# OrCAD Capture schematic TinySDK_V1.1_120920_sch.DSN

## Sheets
1 CORE-PWR: size A3; title: TinySDK V1.1; company: FriendlyARM; note: CORE-PWR
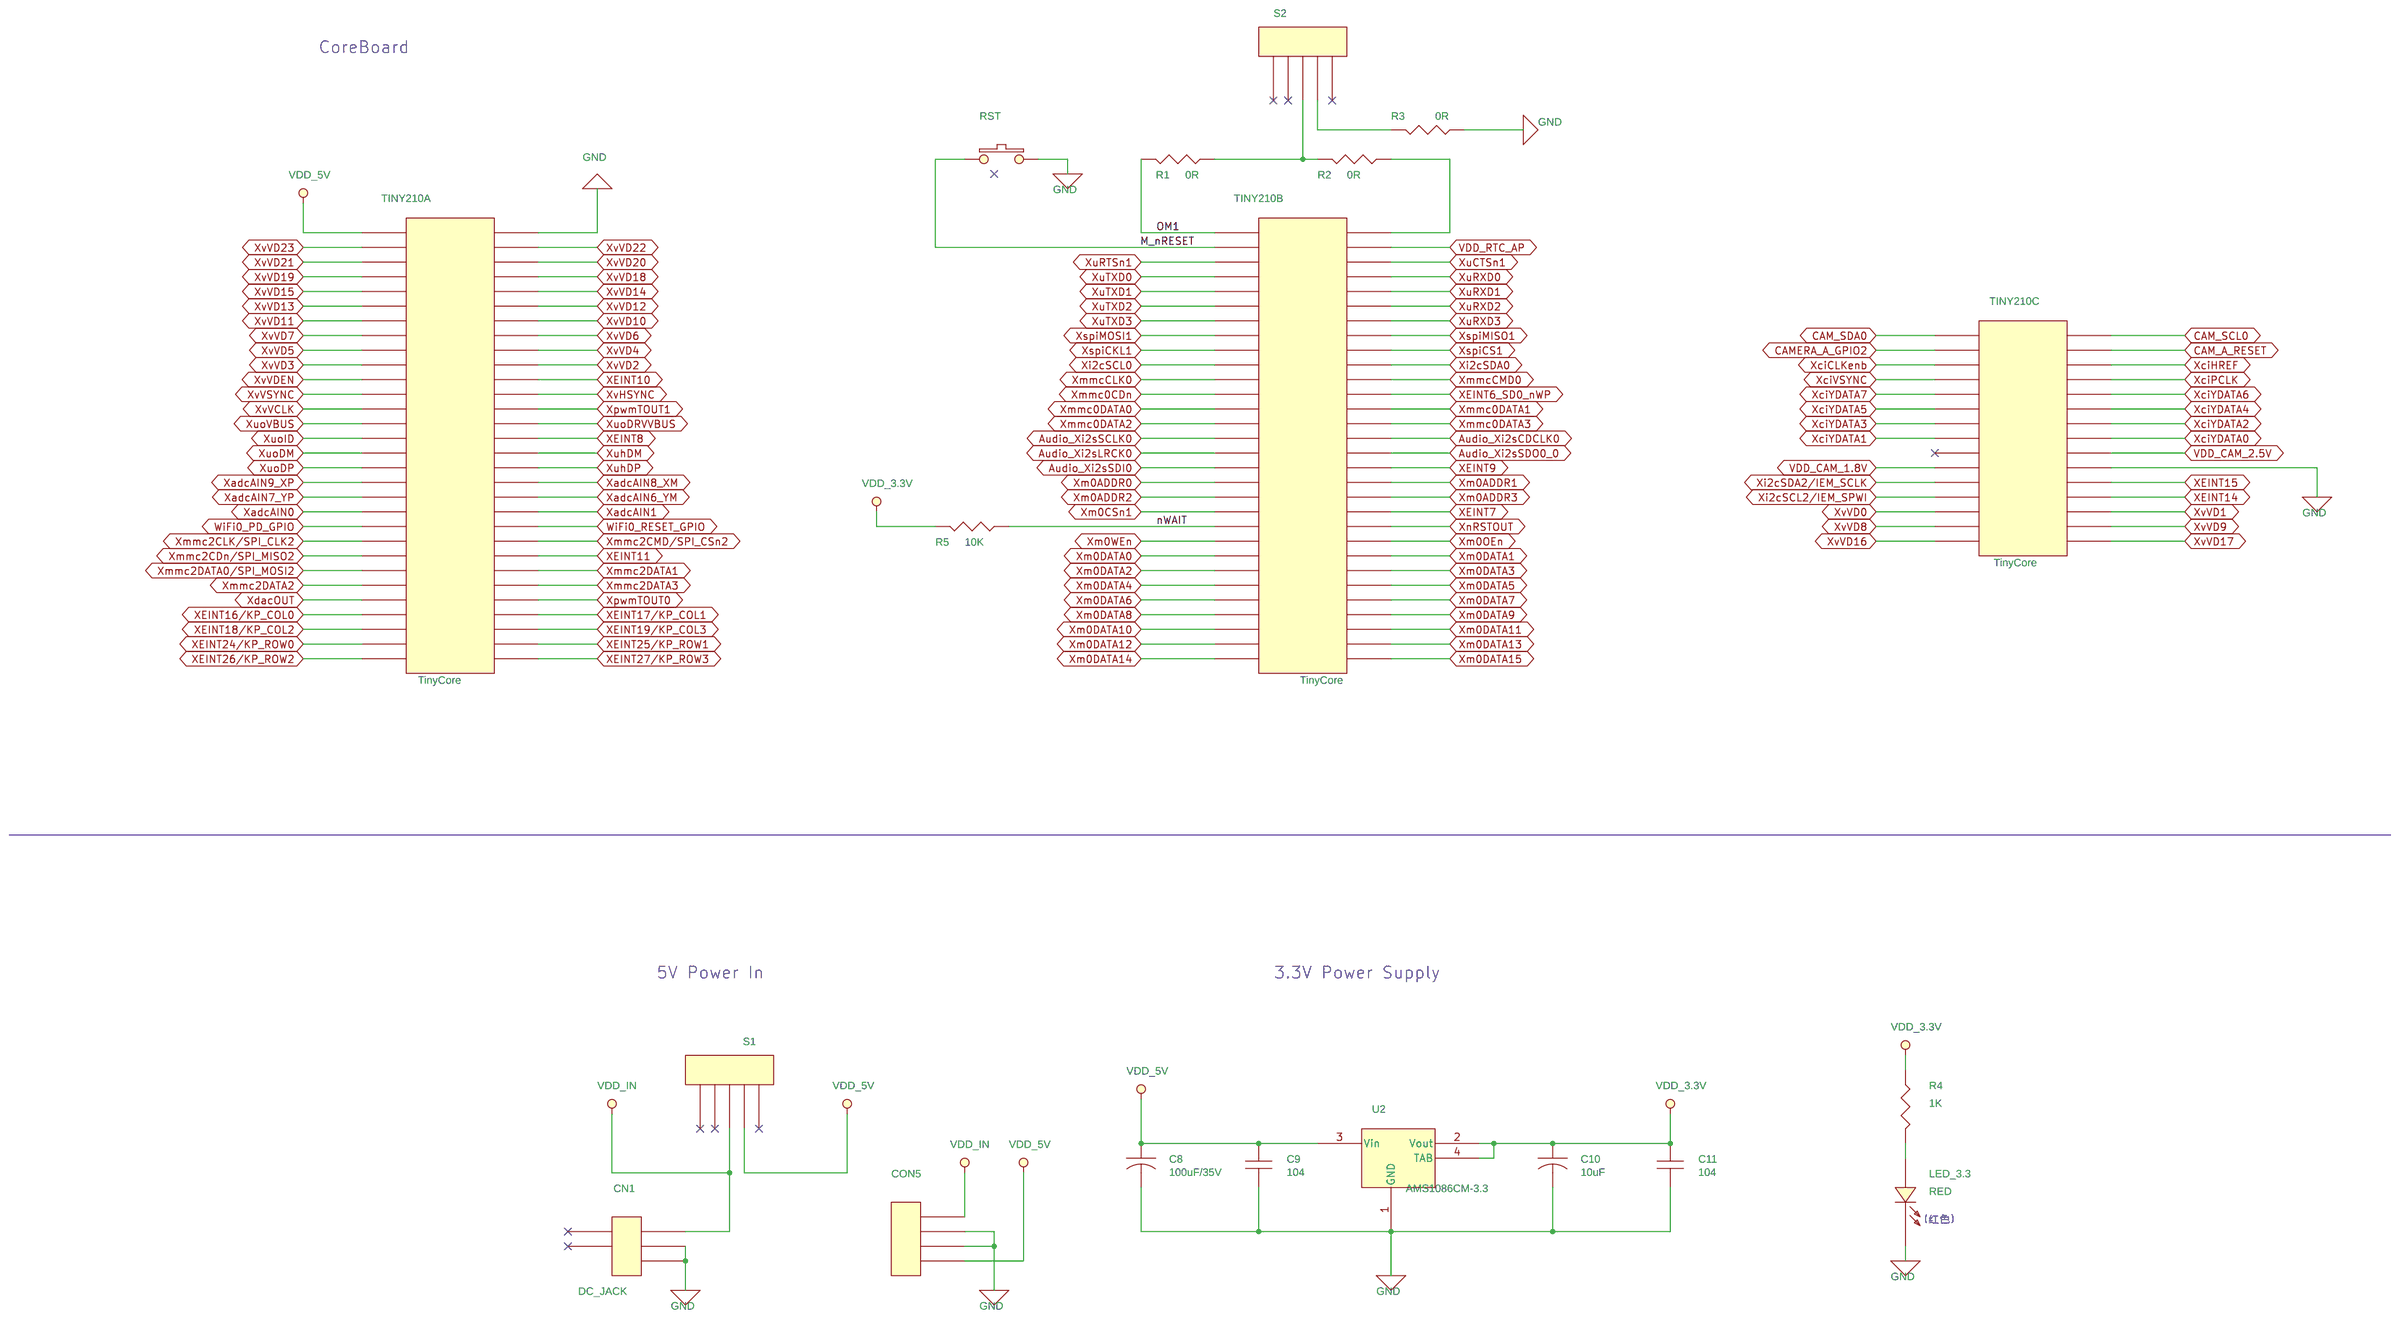
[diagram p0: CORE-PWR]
2 DM9000: size A3; note: DM9000
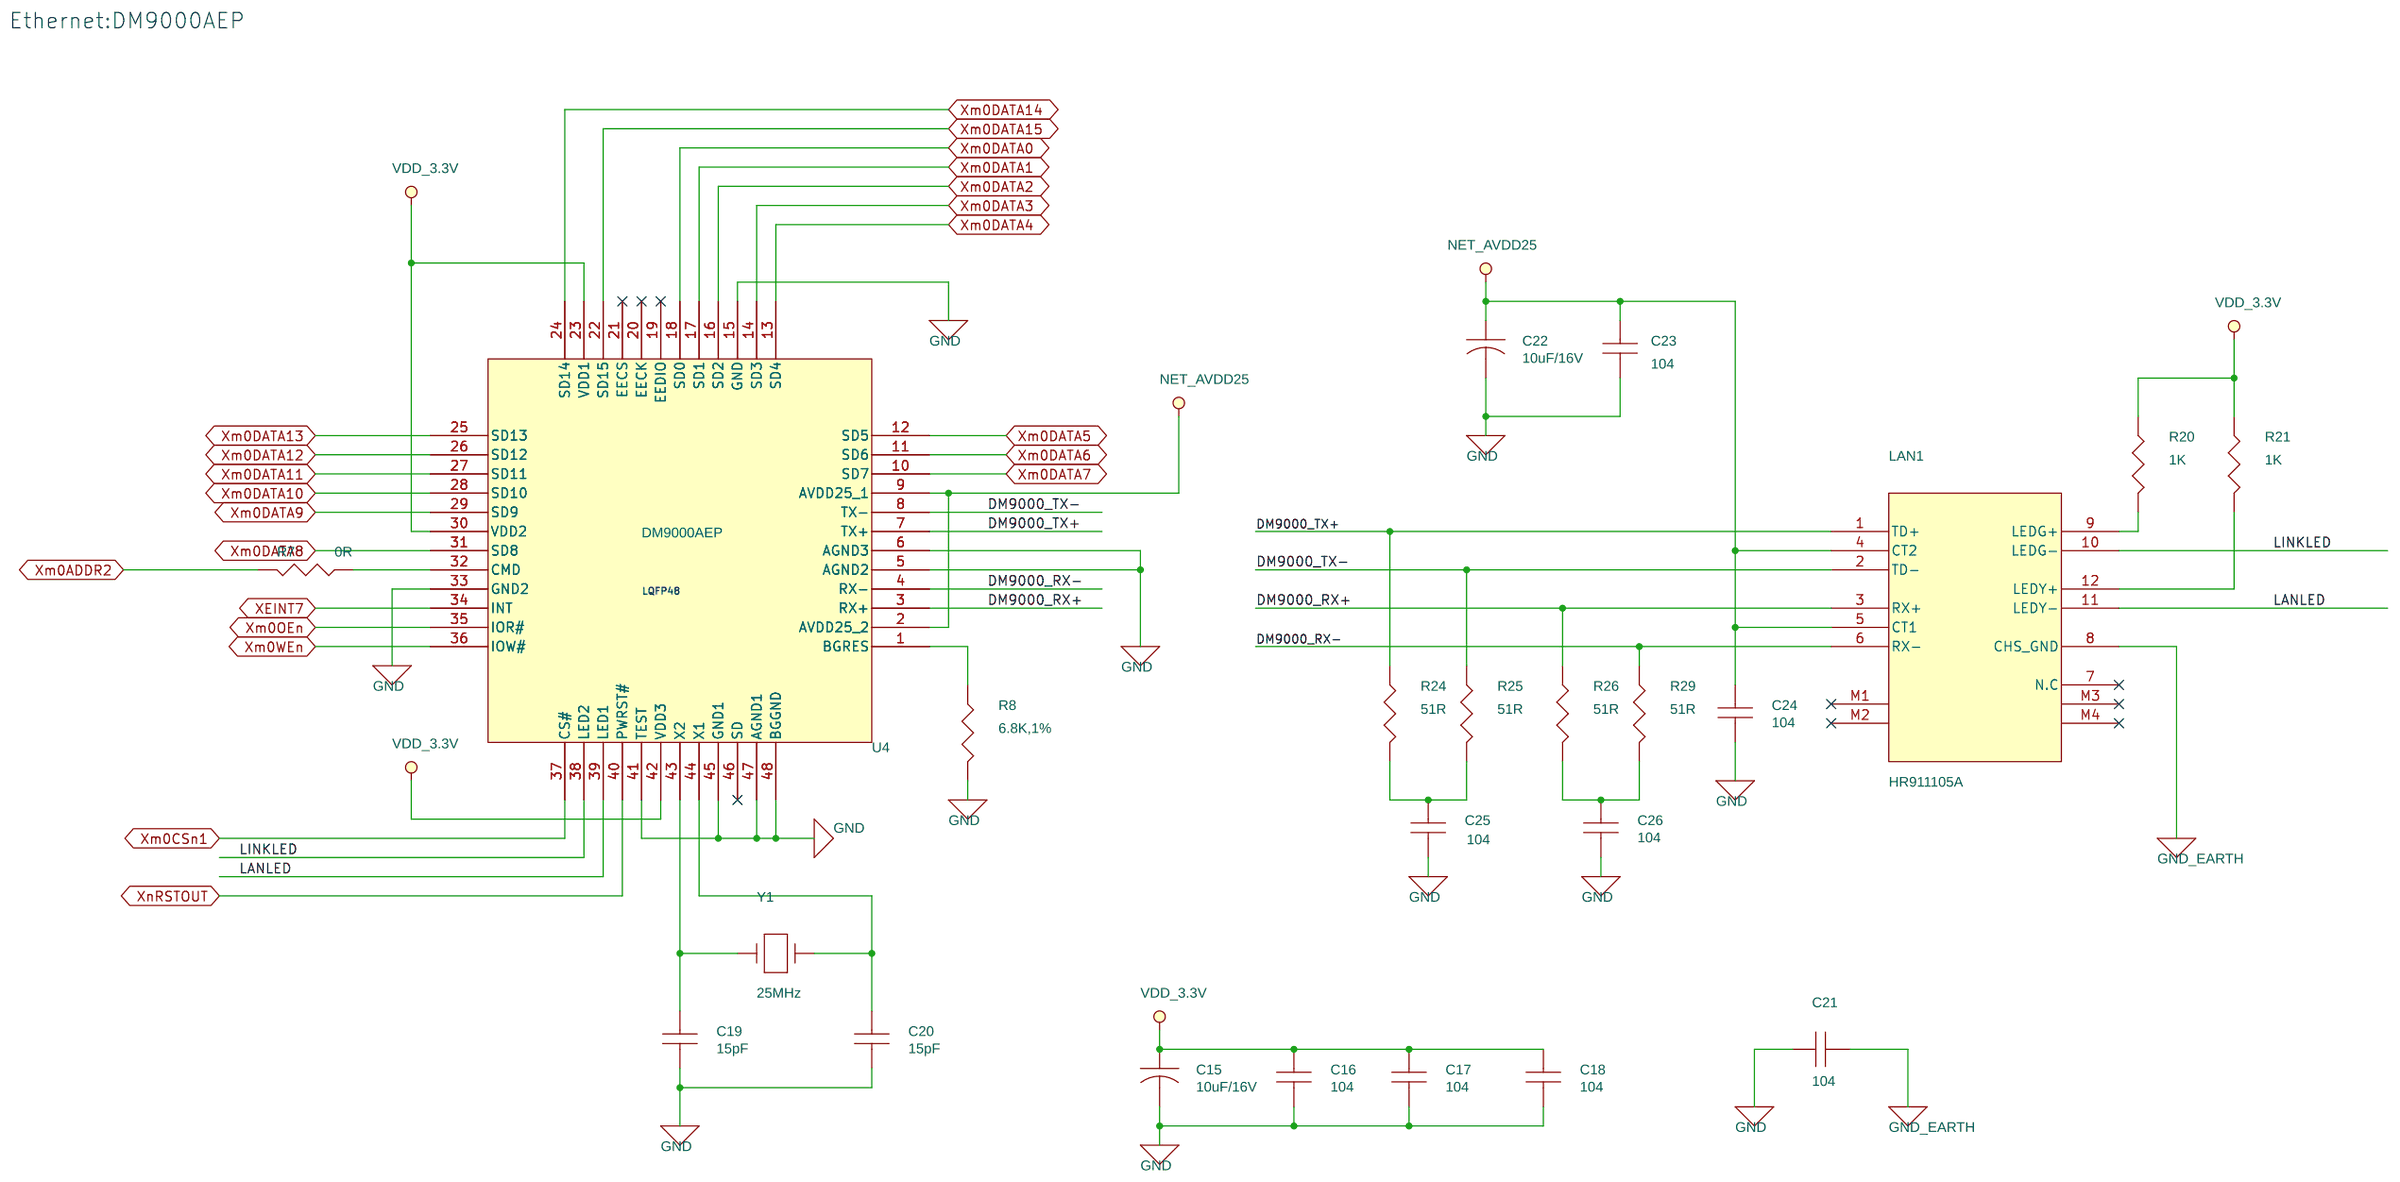
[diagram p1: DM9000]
3 Audio Codec: size A3; note: AUDIO CODEC
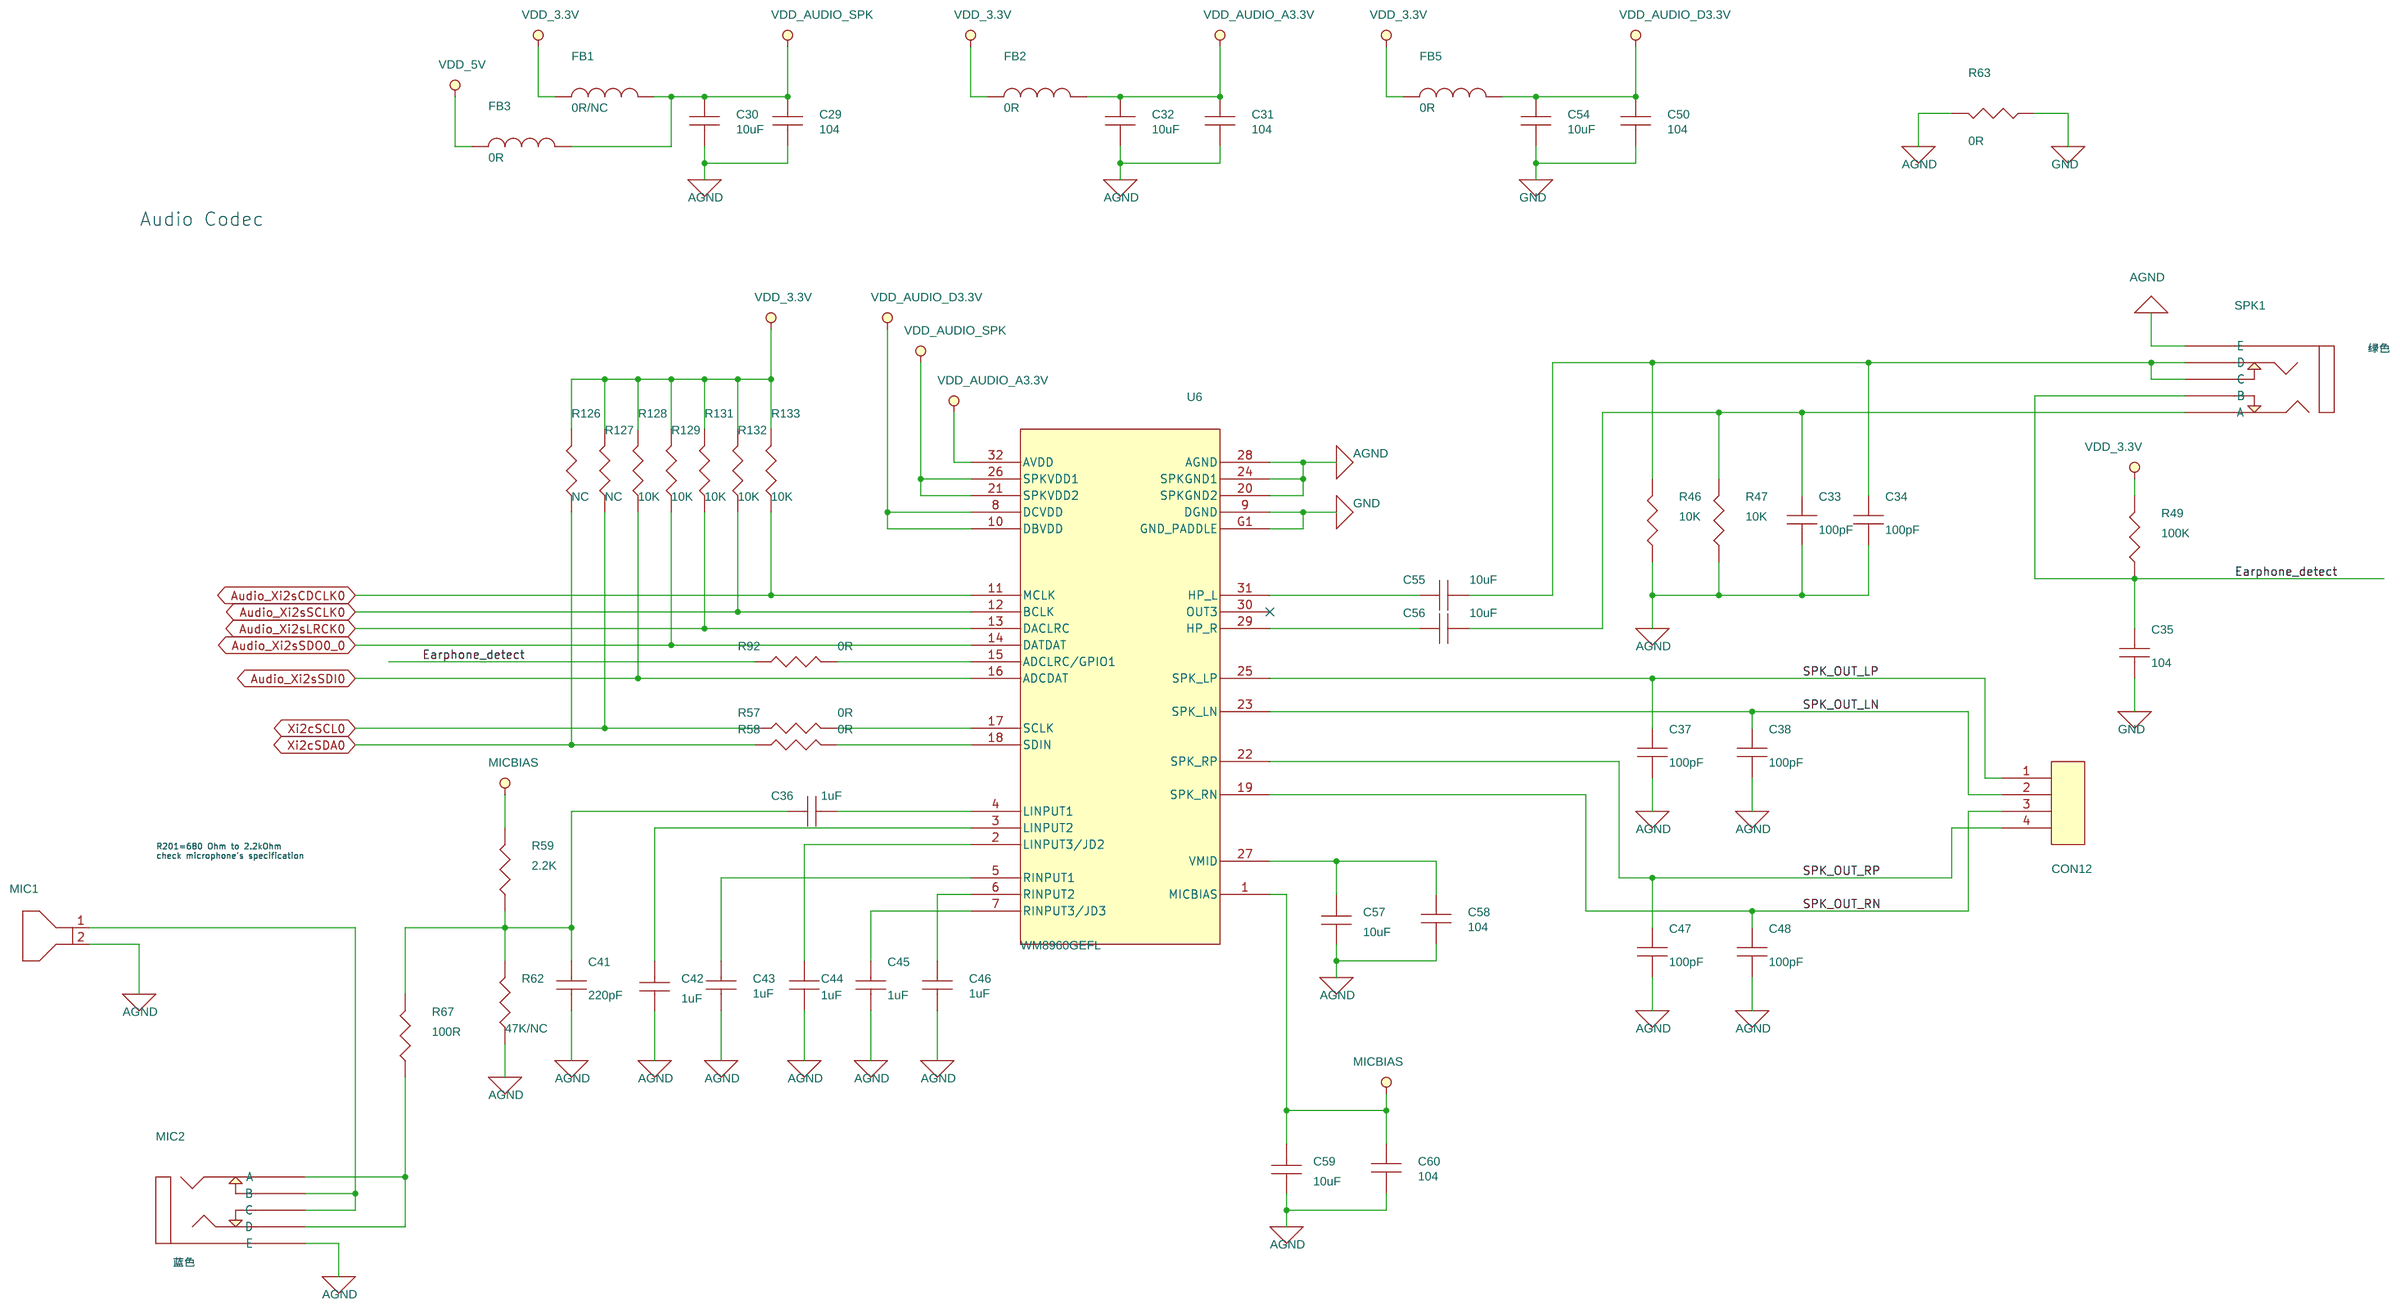
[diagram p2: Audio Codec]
4 SDIO-KEY-ETC: size A3; rev: 1.0; note: SCON-USB-ETC
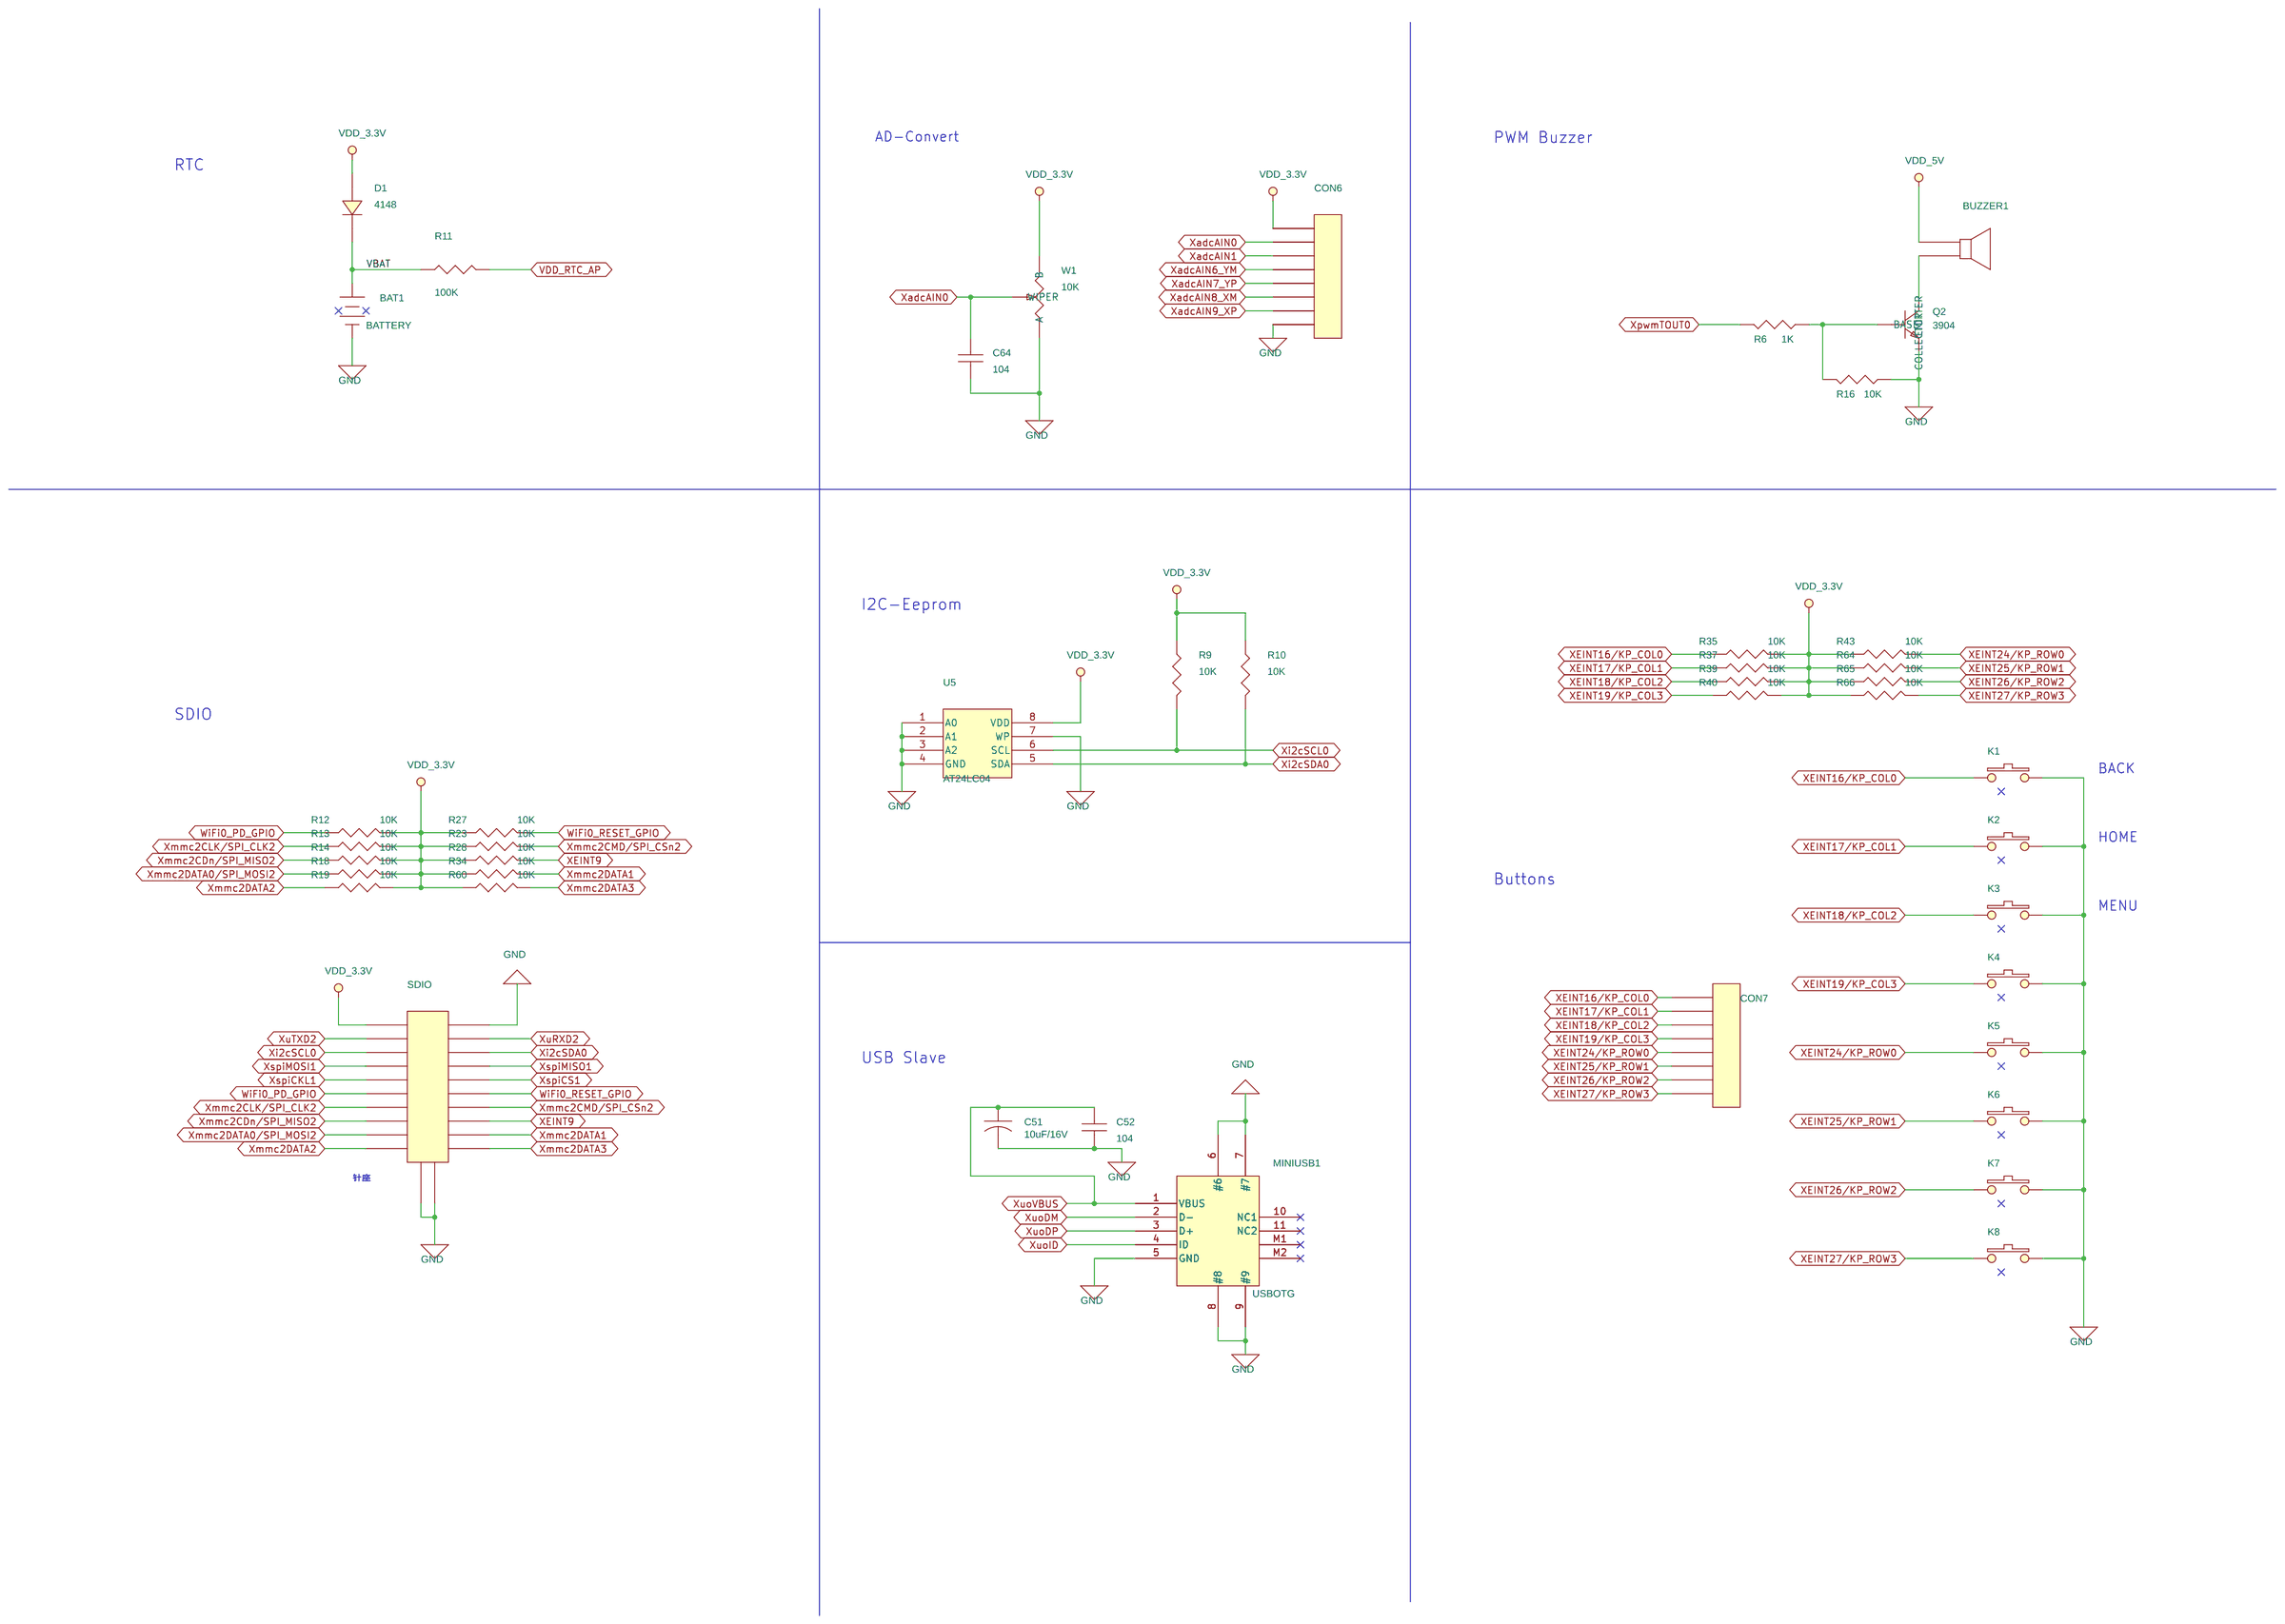
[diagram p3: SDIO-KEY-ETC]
5 LCD-UART-SDCARD-GSensor: size A3; rev: 1.0; note: LCD-UART-SDCARD-GSensor
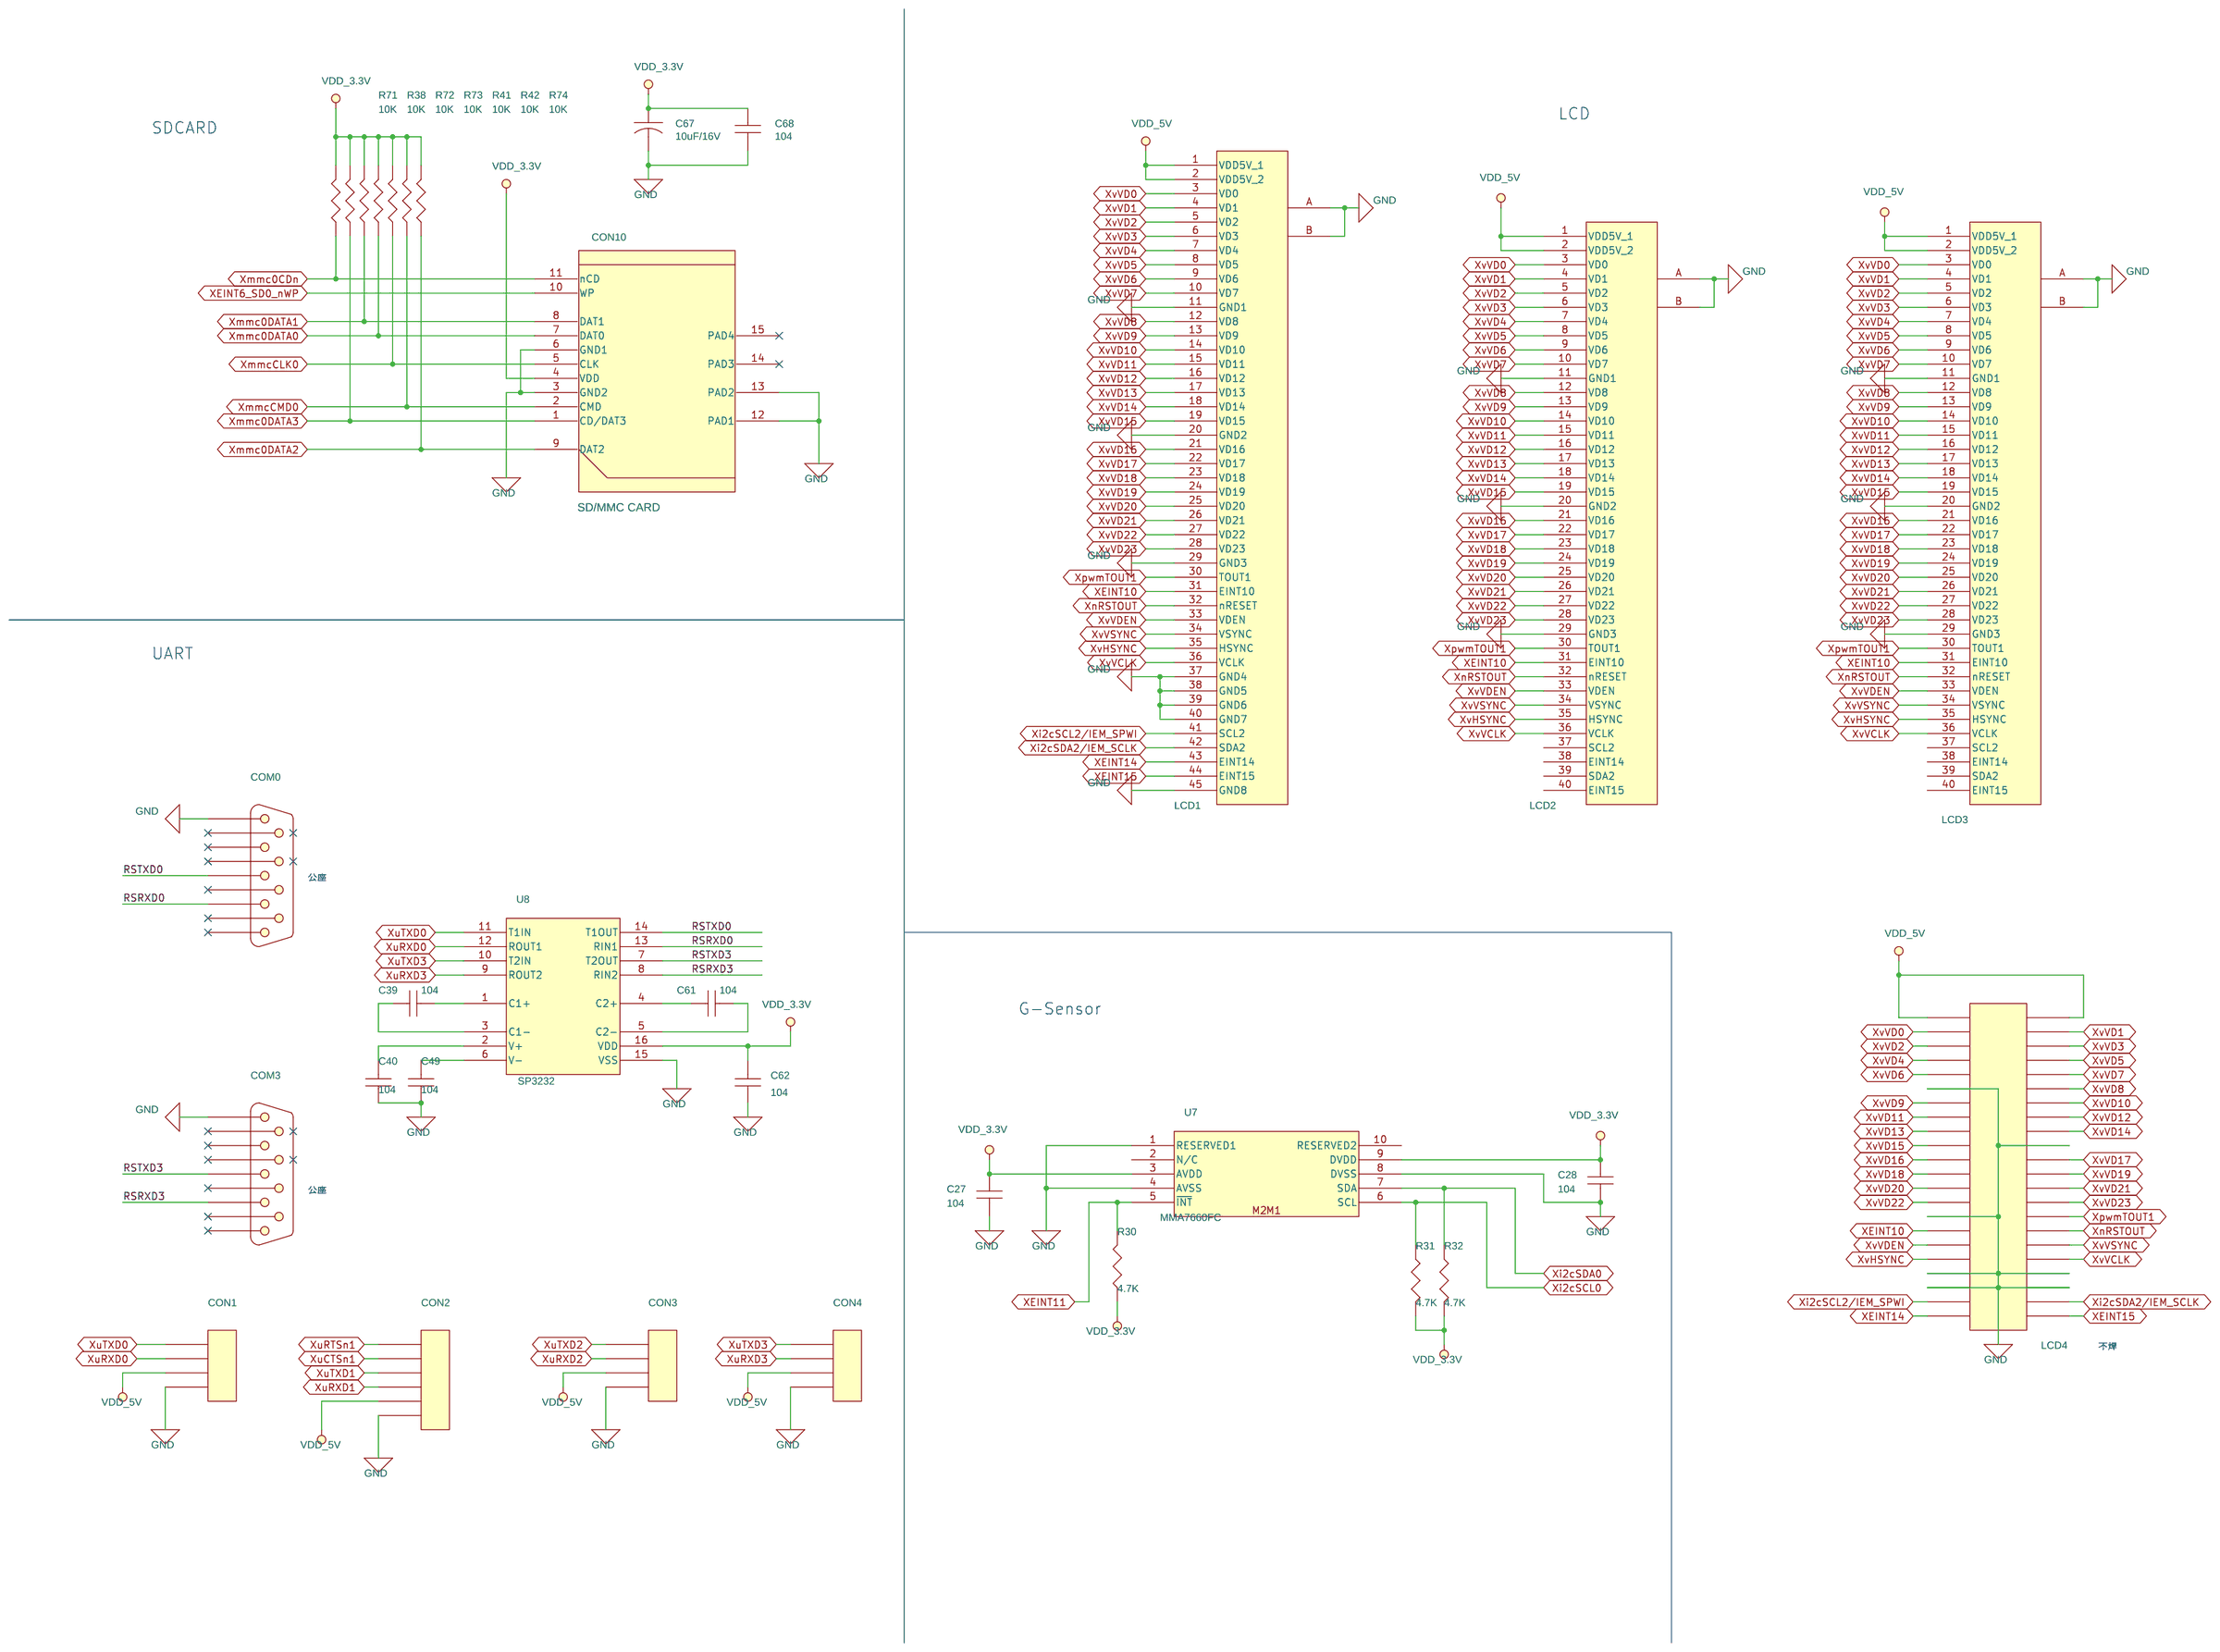
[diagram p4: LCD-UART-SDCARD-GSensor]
6 TVP5150: size A3
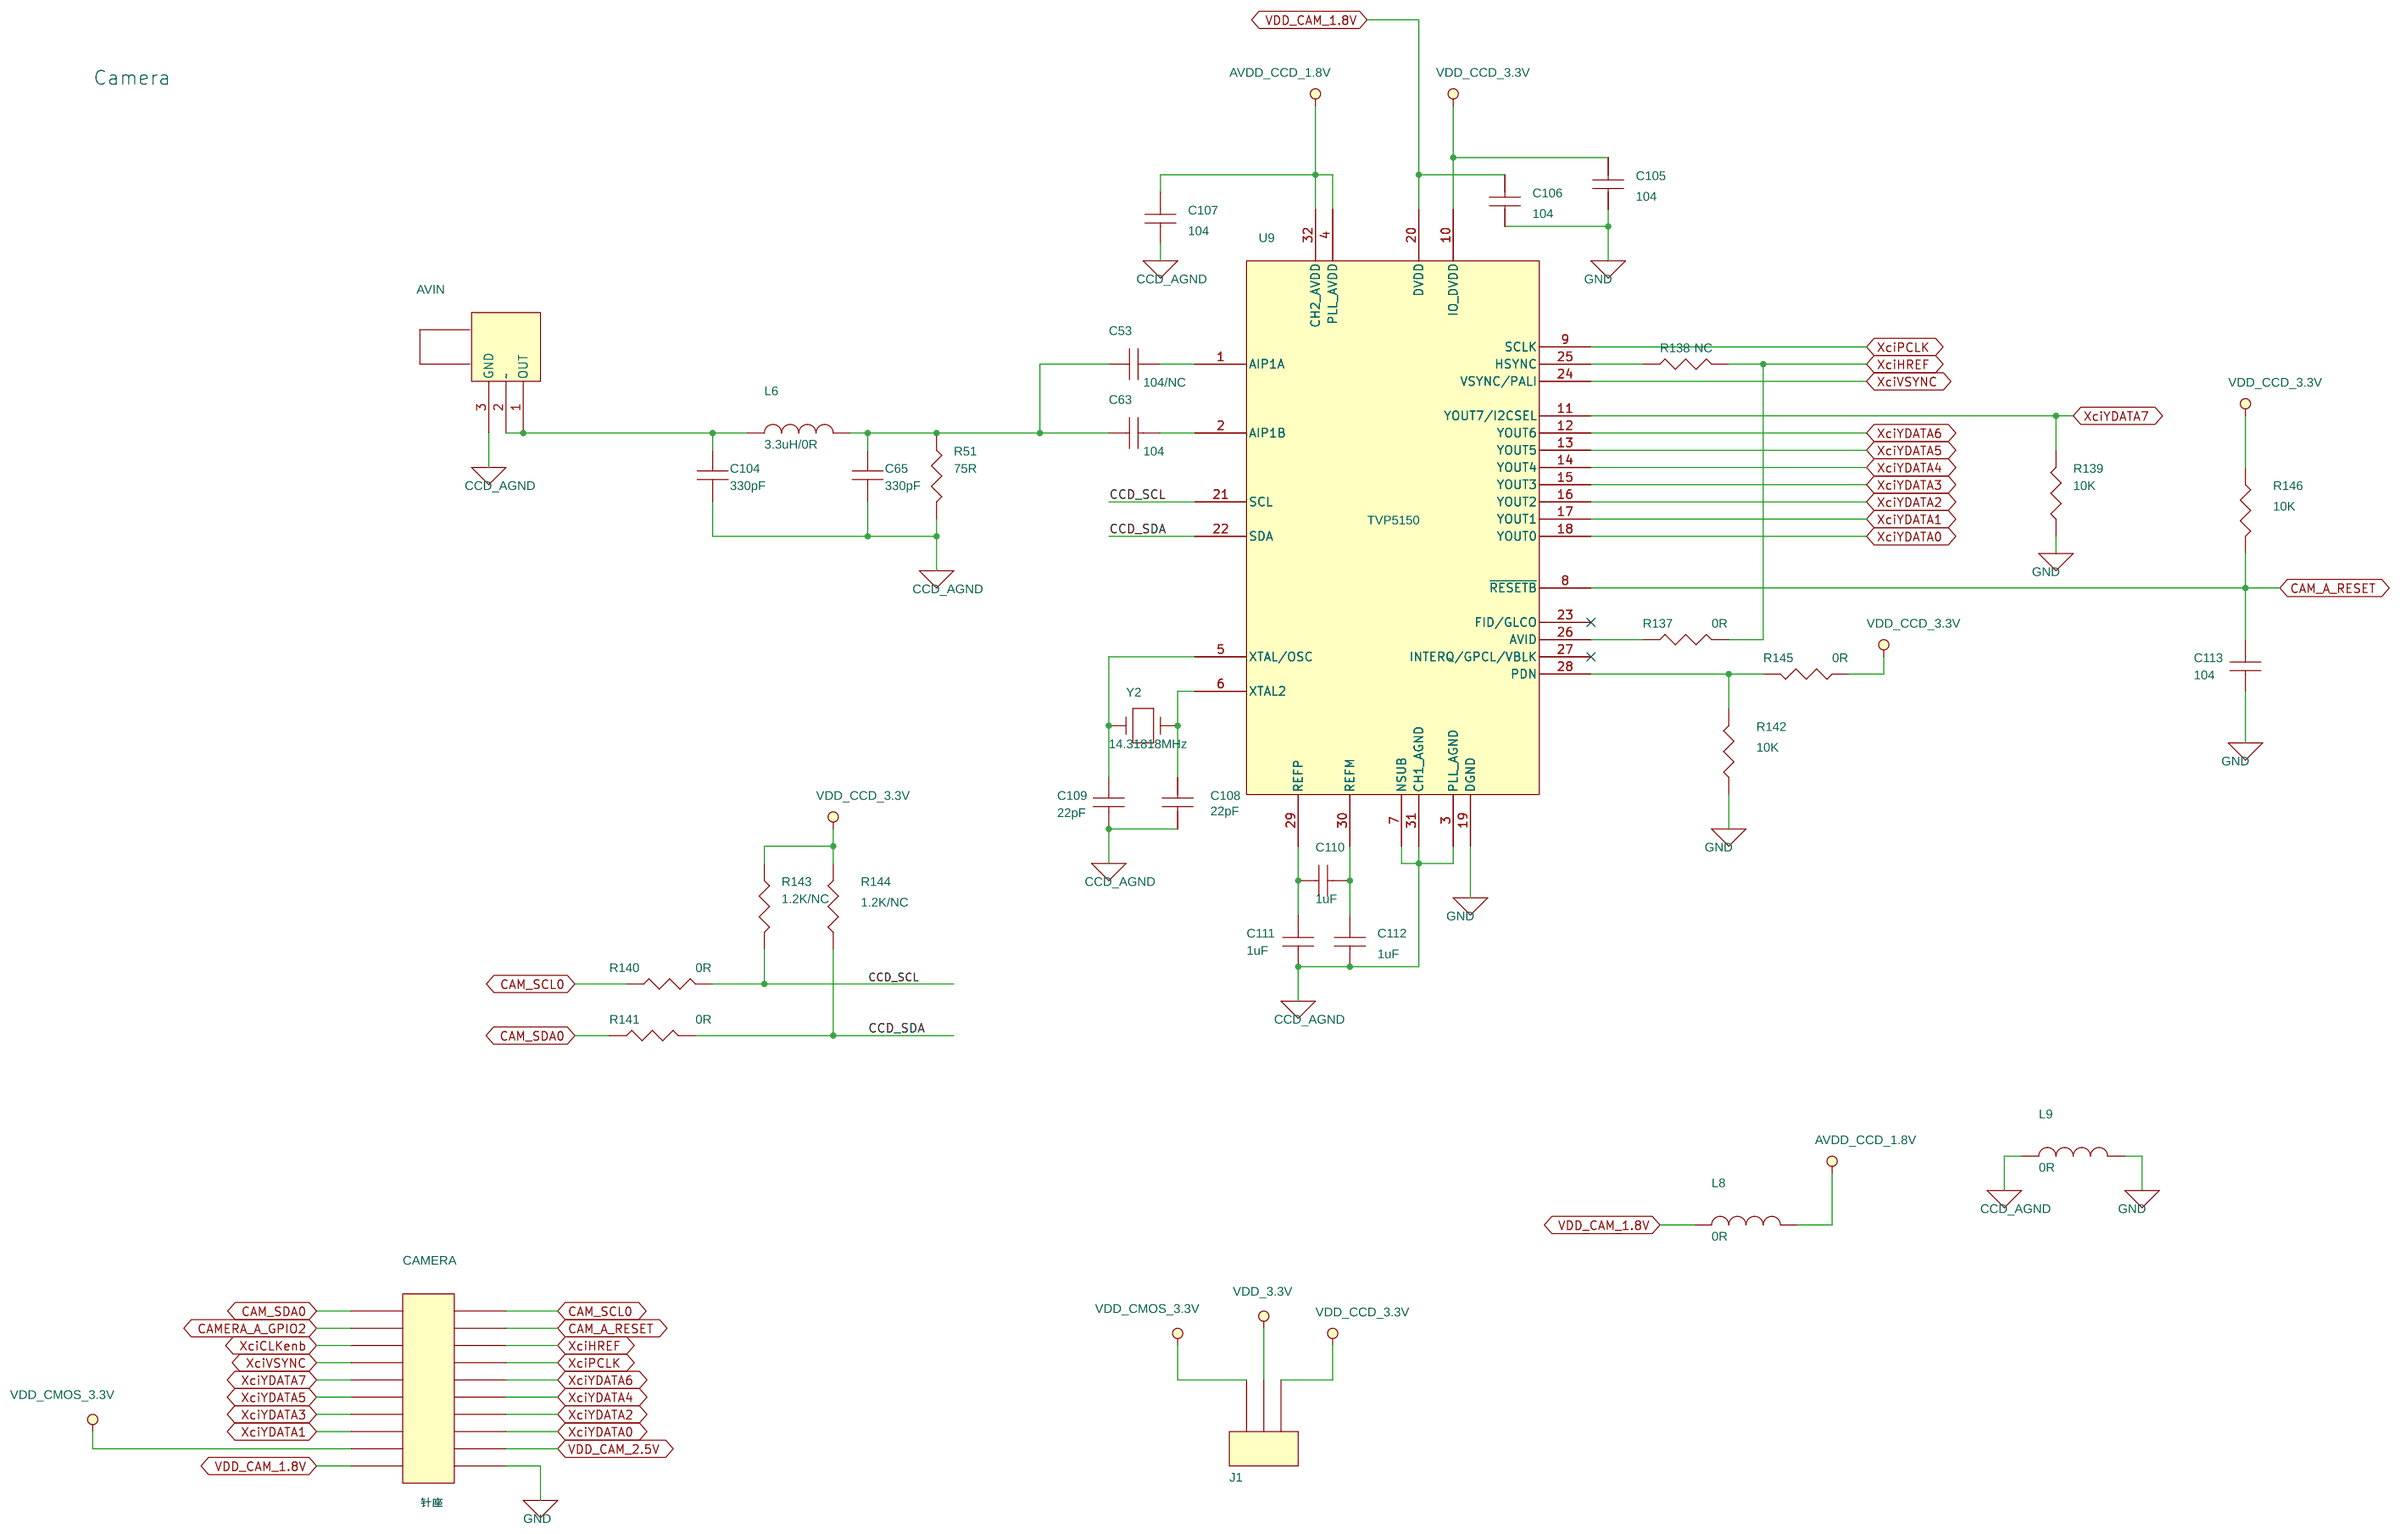
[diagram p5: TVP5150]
7 USB_HUB: size A3
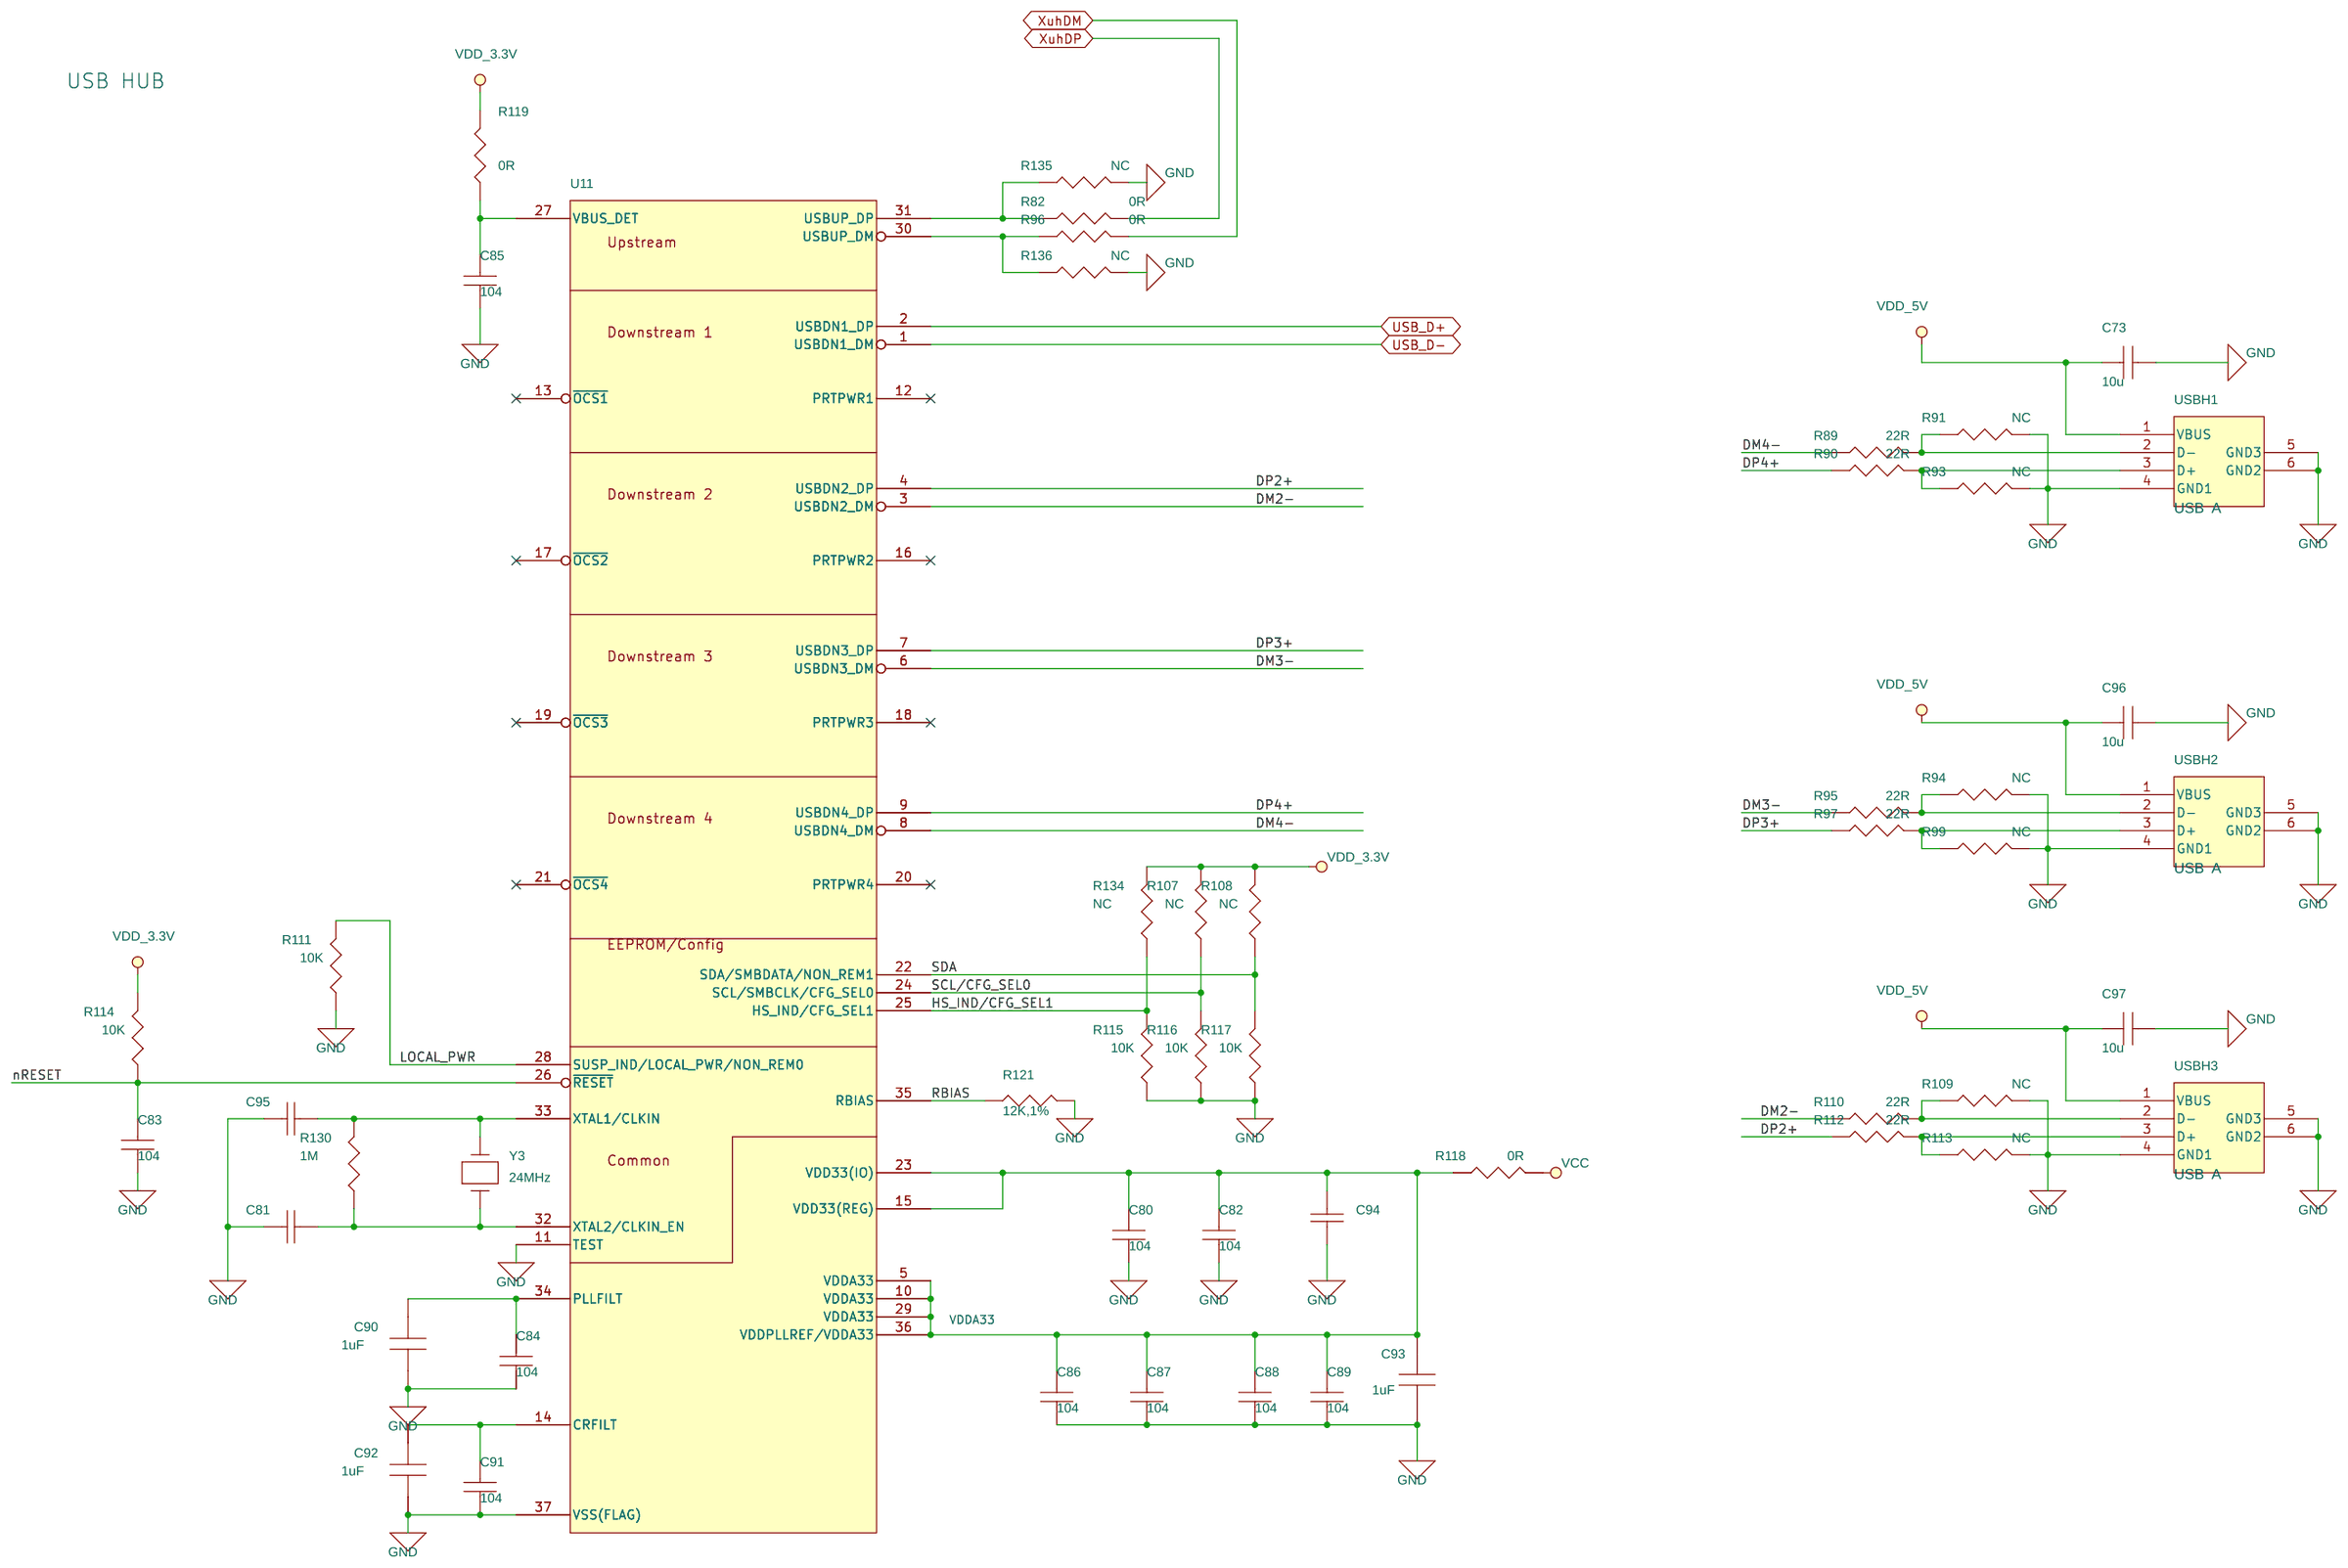
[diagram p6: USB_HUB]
8 3G-miniPCIe: size A3
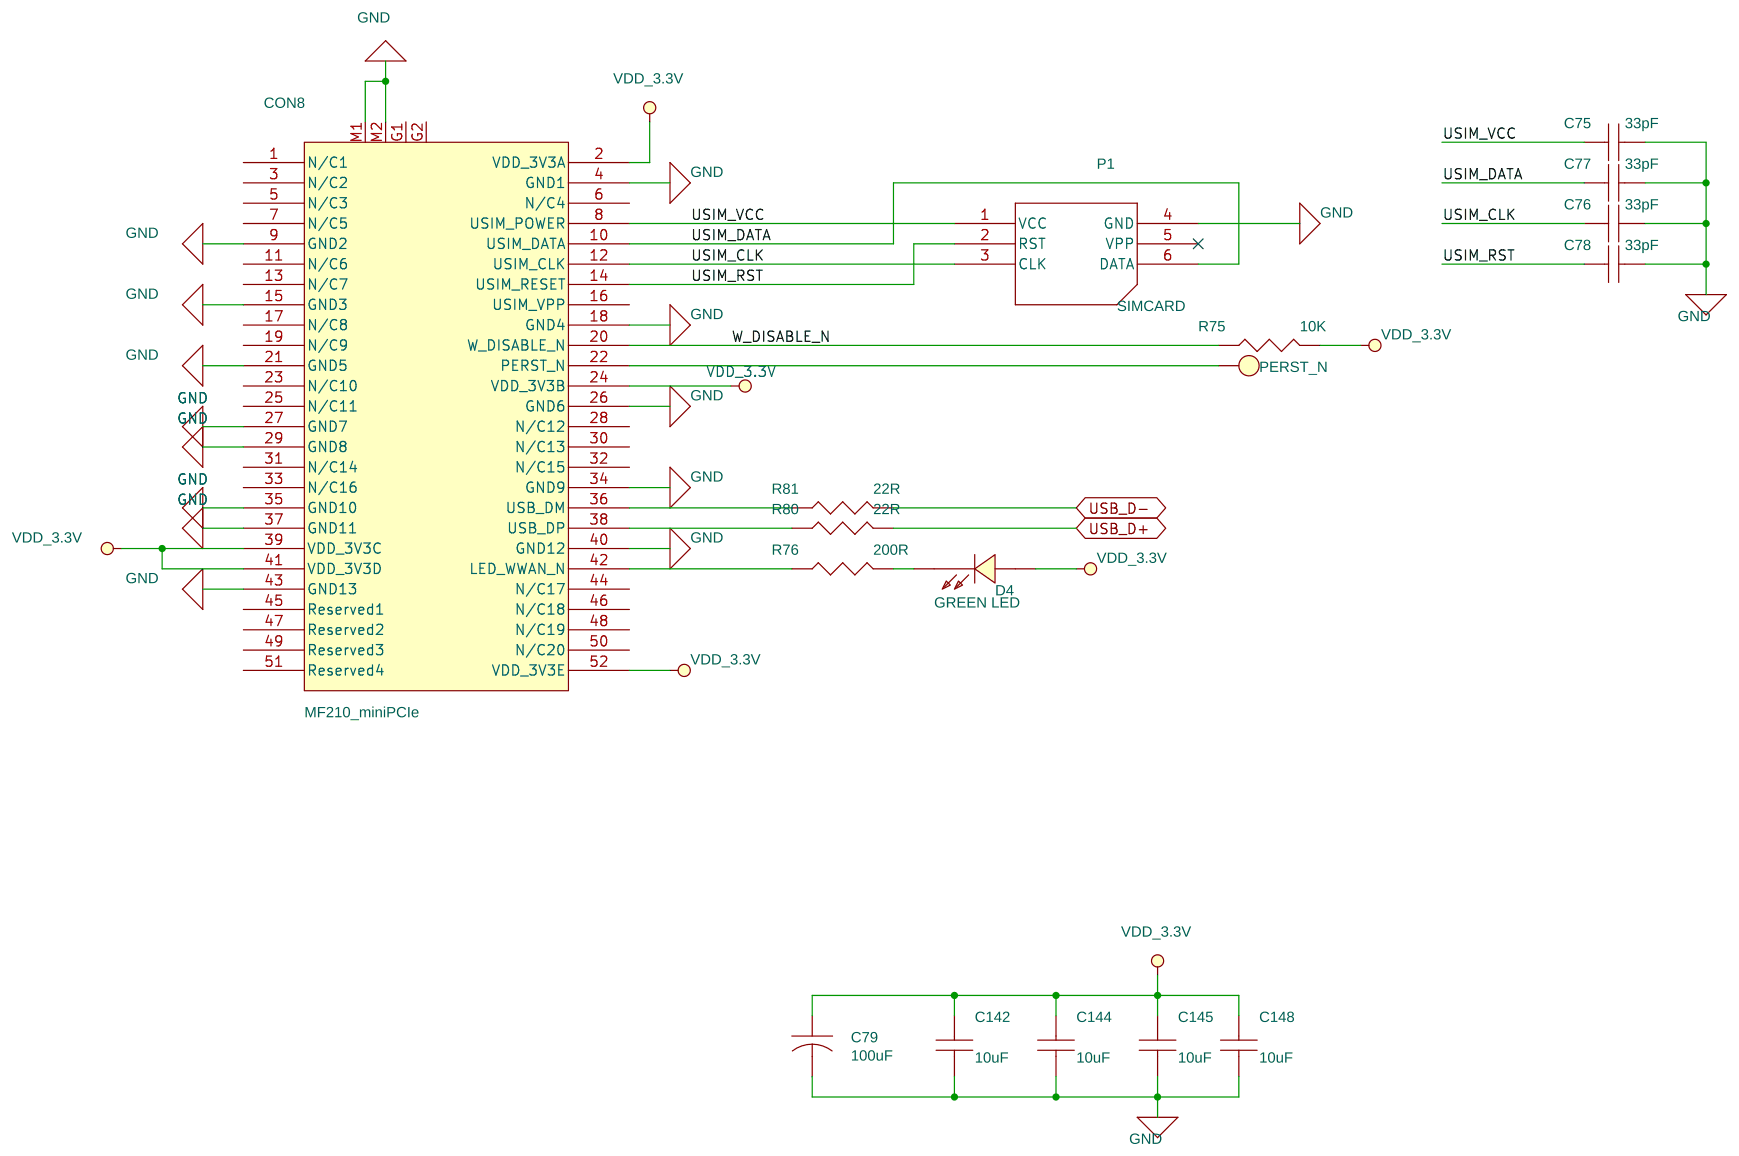
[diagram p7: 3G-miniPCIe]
9 HOLES: size A3; rev: 1.0; note: HOLES
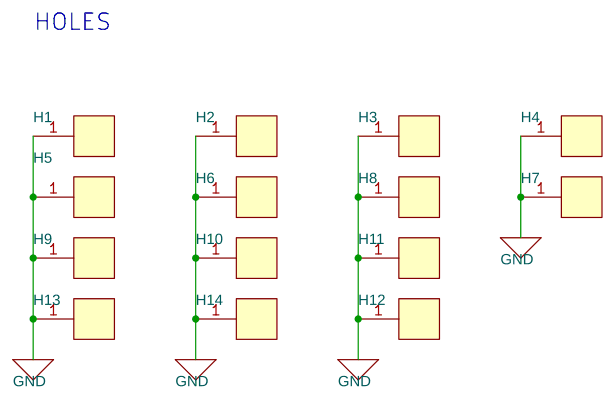
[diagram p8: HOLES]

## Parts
sheet 3G-miniPCIe
C75  33pF  [C0603]
C76  33pF  [C0603]
C77  33pF  [C0603]
C78  33pF  [C0603]
C79  100uF  [c3528]
C142  10uF  [C0805]
C144  10uF  [C0805]
C145  10uF  [C0805]
C148  10uF  [C0805]
CON8  MF210_miniPCIe  [MINI_PCIEX1-52P-4h]
D4  GREEN LED  [LED]
P1  SIMCARD  [sim-0011]
PERST_N  TP  [padc15]
R75  10K  [R0603]
R76  200R  [R0603]
R80  22R  [R0603]
R81  22R  [R0603]
sheet Audio Codec
C29  104  [C0603]
C30  10uF  [C0805]
C31  104  [C0603]
C32  10uF  [C0805]
C33  100pF  [C0603]
C34  100pF  [C0603]
C35  104  [C0603]
C36  1uF  [C0603]
C37  100pF  [C0603]
C38  100pF  [C0603]
C41  220pF  [C0603]
C42  1uF  [C0603]
C43  1uF  [C0603]
C44  1uF  [C0603]
C45  1uF  [C0603]
C46  1uF  [C0603]
C47  100pF  [C0603]
C48  100pF  [C0603]
C50  104  [C0603]
C54  10uF  [C0805]
C55  10uF  [C0805]
C56  10uF  [C0805]
C57  10uF  [C0805]
C58  104  [C0603]
C59  10uF  [C0805]
C60  104  [C0603]
CON12  J1X4_2.0PH  [SIP4-FA]
FB1  0R/NC  [L0603]
FB2  0R  [L0603]
FB3  0R  [L0603]
FB5  0R  [L0603]
MIC1  MIC  [MIC2]
MIC2  PHONEJACK STEREO SW  [EARJACK5]
R46  10K  [R0603]
R47  10K  [R0603]
R49  100K  [R0603]
R57  0R  [R0603]
R58  0R  [R0603]
R59  2.2K  [R0603]
R62  47K/NC  [R0603]
R63  0R  [R0603]
R67  100R  [R0603]
R92  0R  [R0603]
R126  NC  [R0603]
R127  NC  [R0603]
R128  10K  [R0603]
R129  10K  [R0603]
R131  10K  [R0603]
R132  10K  [R0603]
R133  10K  [R0603]
SPK1  PHONEJACK STEREO SW  [EARJACK5]
U6  WM8960GEFL  [QFN32-19P7-TH]
sheet CORE-PWR
C8  100uF/35V  [CAPSOP]
C9  104  [C0603]
C10  10uF  [c0805]
C11  104  [C0603]
CN1  DC_JACK  [DC023B]
CON5  CON4  [CON4-B]
LED_3.3  RED  [LED]
R1  0R  [R0603]
R2  0R  [R0603]
R3  0R  [R0603]
R4  1K  [R0603]
R5  10K  [R0603]
RST  SW PUSHBUTTON  [KEY-A06]
S1  SW-DIP4  [SW35]
S2  SW-DIP4  [SW35]
TINY210  TinyCore  [TINY6410_2]  (sections A,B,C)
U2  AMS1086CM-3.3  [TO-252]
sheet DM9000
C15  10uF/16V  [c0805]
C16  104  [C0603]
C17  104  [C0603]
C18  104  [C0603]
C19  15pF  [C0603]
C20  15pF  [C0603]
C21  104  [C0603]
C22  10uF/16V  [c0805]
C23  104  [C0603]
C24  104  [C0603]
C25  104  [C0603]
C26  104  [C0603]
LAN1  HR911105A  [HR911105A]
R7  0R  [R0603]
R8  6.8K,1%  [R0603]
R20  1K  [R0603]
R21  1K  [R0603]
R24  51R  [R0603]
R25  51R  [R0603]
R26  51R  [R0603]
R29  51R  [R0603]
U4  DM9000AEP  [LQFP48FA]
Y1  25MHz  [OSC2PR-1]
sheet HOLES
H1  CON1  [H1]
H2  CON1  [H1]
H3  CON1  [H1]
H4  CON1  [H1]
H5  CON1  [H1]
H6  CON1  [H1]
H7  CON1  [H1]
H8  CON1  [H1]
H9  CON1  [H1]
H10  CON1  [H1]
H11  CON1  [H1]
H12  CON1  [H1]
H13  CON1  [H1]
H14  CON1  [H1]
sheet LCD-UART-SDCARD-GSensor
C27  104  [C0603]
C28  104  [C0603]
C39  104  [C0603]
C40  104  [C0603]
C49  104  [C0603]
C61  104  [C0603]
C62  104  [C0603]
C67  10uF/16V  [c0805]
C68  104  [C0603]
COM0  CONNECTOR DB9  [DB9RA_M]
COM3  CONNECTOR DB9  [DB9RA_M]
CON1  CON4  [SIP4-FA2]
CON2  CON6  [SIP6-FA2]
CON3  CON4  [SIP4-FA2]
CON4  CON4  [SIP4-FA2]
CON10  SD/MMC CARD  [SDCARD]
LCD1  LCD-888  [CON-FPC-P05-45P]
LCD2  LCD-888  [CON-FPC-P05-40P]
LCD3  LCD-888  [CON-FPC-P05-40P]
LCD4  CON44A  [IDC44S2]
R30  4.7K  [R0603]
R31  4.7K  [R0603]
R32  4.7K  [R0603]
R38  10K  [R0603]
R41  10K  [R0603]
R42  10K  [R0603]
R71  10K  [R0603]
R72  10K  [R0603]
R73  10K  [R0603]
R74  10K  [R0603]
U7  MMA7660FC  [DFN10-19P7X111-2TH]
U8  SP3232  [SOP16]
sheet SDIO-KEY-ETC
BAT1  BATTERY  [BAT600]
BUZZER1  SPEAKER  [SPEAKER]
C51  10uF/16V  [c0805]
C52  104  [C0603]
C64  104  [C0603]
CON6  CON8  [SIP8-FA2]
CON7  CON8  [SIP8-FA2]
D1  4148  [D1206]
K1  SW PUSHBUTTON  [KEY-A06]
K2  SW PUSHBUTTON  [KEY-A06]
K3  SW PUSHBUTTON  [KEY-A06]
K4  SW PUSHBUTTON  [KEY-A06]
K5  SW PUSHBUTTON  [KEY-A06]
K6  SW PUSHBUTTON  [KEY-A06]
K7  SW PUSHBUTTON  [KEY-A06]
K8  SW PUSHBUTTON  [KEY-A06]
MINIUSB1  USBOTG  [miniUSB_ant]
Q2  3904  [SOT-23-Q]
R6  1K  [R0603]
R9  10K  [R0603]
R10  10K  [R0603]
R11  100K  [R0603]
R12  10K  [R0603]
R13  10K  [R0603]
R14  10K  [R0603]
R16  10K  [R0603]
R18  10K  [R0603]
R19  10K  [R0603]
R23  10K  [R0603]
R27  10K  [R0603]
R28  10K  [R0603]
R34  10K  [R0603]
R35  10K  [R0603]
R37  10K  [R0603]
R39  10K  [R0603]
R40  10K  [R0603]
R43  10K  [R0603]
R60  10K  [R0603]
R64  10K  [R0603]
R65  10K  [R0603]
R66  10K  [R0603]
SDIO  CON20A  [sdwifi-2h]
U5  AT24LC04  [SOP8]
W1  10K  [VR3_7X7]
sheet TVP5150
AVIN  TVOUT  [tvout]
C53  104/NC  [c0603]
C63  104  [c0603]
C65  330pF  [c0603]
C104  330pF  [c0603]
C105  104  [c0603]
C106  104  [c0603]
C107  104  [c0603]
C108  22pF  [c0603]
C109  22pF  [c0603]
C110  1uF  [c0603]
C111  1uF  [c0603]
C112  1uF  [c0603]
C113  104  [c0603]
CAMERA  CON20A  [sdwifi-nh]
J1  CON3  [SIP3s]
L6  3.3uH/0R  [L0603]
L8  0R  [L0603]
L9  0R  [L0603]
R51  75R  [R0603]
R137  0R  [R0603]
R138  NC  [R0603]
R139  10K  [R0603]
R140  0R  [R0603]
R141  0R  [R0603]
R142  10K  [R0603]
R143  1.2K/NC  [R0603]
R144  1.2K/NC  [R0603]
R145  0R  [R0603]
R146  10K  [R0603]
U9  TVP5150  [s-pqfp-g32]
Y2  14.31818MHz  [OSC2PR-1]
sheet USB_HUB
C73  10u  [c0805]
C80  104  [c0603]
C81  33pF  [c0603]
C82  104  [c0603]
C83  104  [c0603]
C84  104  [c0603]
C85  104  [c0603]
C86  104  [c0603]
C87  104  [c0603]
C88  104  [c0603]
C89  104  [c0603]
C90  1uF  [c0603]
C91  104  [c0603]
C92  1uF  [c0603]
C93  1uF  [c0603]
C94  1uF  [c0603]
C95  33pF  [c0603]
C96  10u  [c0805]
C97  10u  [c0805]
R82  0R  [r0603]
R89  22R  [r0603]
R90  22R  [r0603]
R91  NC  [r0603]
R93  NC  [r0603]
R94  NC  [r0603]
R95  22R  [r0603]
R96  0R  [r0603]
R97  22R  [r0603]
R99  NC  [r0603]
R107  NC  [r0603]
R108  NC  [r0603]
R109  NC  [r0603]
R110  22R  [r0603]
R111  10K  [r0603]
R112  22R  [r0603]
R113  NC  [r0603]
R114  10K  [r0603]
R115  10K  [r0603]
R116  10K  [r0603]
R117  10K  [r0603]
R118  0R  [r0603]
R119  0R  [r0603]
R121  12K,1%  [r0603]
R130  1M  [r0603]
R134  NC  [r0603]
R135  NC  [r0603]
R136  NC  [r0603]
U11  USB2514B_QFN36_MIN  [QFN36-19P7]
USBH1  USB  A  [USB-A2]
USBH2  USB  A  [USB-A2]
USBH3  USB  A  [USB-A2]
Y3  24MHz  [OSC2PR-1]

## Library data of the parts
C9 C11 C16-C21 C23-C50 C52-C65 C68 C73 C75-C78 C96 C97 C104-C113 C142 C144 C145 C148 = CAP_NP
C8 C10 C15 C22 C51 C67 C79 = CAP
CON8 = CON50A_5
D4 LED_3.3 = LED
P1 = SIMCARD_0
PERST_N = TP
R1-R14 R16 R18-R21 R23-R32 R34 R35 R37-R43 R46 R47 R49 R57-R60 R62-R67 R71-R76 R80-R82 R89-R97 R99 R107-R119 R126-R136 = R
CON12 = J1X4_1: Text Field1: 20; Text Field2: 50
FB1-FB3 FB5 L6 L8 L9 = INDUCTOR
MIC1 = MIC
MIC2 SPK1 = PHONEJACK_STEREO_SW
U6 = WM8960GEFL_0: Text Field1: 120; Text Field2: 310
CN1 = CON3_3
CON1 CON3-CON5 = CON4
K1-K8 RST = SW_PUSHBUTTON_0
S1 S2 = CON5
TINY210 = TinyCore
U2 = AMS1117
LAN1 = HR911105A: Text Field1: 90; Text Field2: 140
U4 = DM9000AEP
Y1-Y3 = CRYSTAL
H1-H14 = CON1
COM0 COM3 = CONNECTOR_DB9_2
CON2 = CON6
CON10 = SD_0
LCD1 = LCD-888_1
LCD2 LCD3 = LCD-888_2
LCD4 = CON40A_0
U7 = MMA7660FC
U8 = SP3232
BAT1 = BATTERY_3
BUZZER1 = SPEAKER
CON6 CON7 = CON8
D1 = DIODE
MINIUSB1 = USB_A_B_2: Text Field1: 60; Text Field2: 80
Q2 = NPN-BEC
SDIO = CON20A_4
U5 = AT24LC04
W1 = RESISTOR_VAR_0
AVIN = TVOUT
CAMERA = CON20A
J1 = CON3
R51 R137-R146 = RESISTOR
U9 = TVP5150
C80 C82-C89 C91 = CAP_NP: PAGE: 14
C81 C94 C95 = C: 贴片电容 100nF 25V ±10% X7R 0603; CATALOG: 0603 贴片电容(MLCC); MANUFACTURER: 0603B104K250NT; MATERIAL: X7R; PART_NUMBER: 1104.00100; PRECISION: ±10%; RATED_VOLTAGE: 25V; ROHS: Y; VERSION: A.2; Datasheet: http://vplm.vtroncorp.com:8070/Windchill/servlet/TypeBasedIncludeServlet?tlnType=object&oid=VR:wt.part.WTPart:1352738&tlnActio
C90 C92 = 1.0uF-6.3V-10%-X5R-0402
C93 = 1.0uF-16V-10%-X5R-0603: DNP: DNP; Device: CAP0603
R121 = 12.0K-1_16W-1%-0603: Device: RES0603
U11 = USB2514B_QFN36_MIN
USBH1-USBH3 = USBPORT_0

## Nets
AGND: C29.2 C30.2 C31.2 C32.2 C33.2 C34.2 C37.2 C38.2 C41.2 C42.1 C43.2 C44.2 C45.2 C46.2 C47.2 C48.2 C57.1 C58.2 C59.1 C60.2 MIC1.2 MIC2.5(E) R46.1 R47.1 R62.1 R63.2 SPK1.5(E) U6.20(SPKGND2) U6.24(SPKGND1) U6.28(AGND)
AVDD_CCD_1.8V: C107.2 L8.2 U9.4(PLL_AVDD) U9.32(CH2_AVDD)
GND: BAT1.2(-) C8.2 C9.2 C10.2 C11.2 C15.2 C16.2 C17.2 C18.2 C19.2 C20.2 C21.1 C22.2 C23.2 C24.2 C25.2 C26.2 C27.2 C28.2 C35.2 C40.1 C49.1 C50.2 C51.2 C52.2 C54.2 C62.1 C64.2 C67.2 C68.2 C73.2 C75.2 C76.2 C77.2 C78.2 C79.2 C80.2 C81.2 C82.2 C83.2 C84.2 C85.2 C86.2 C87.2 C88.2 C89.2 C90.2 C91.2 C92.2 C93.2 C94.2 C95.2 C96.2 C97.2 C105.1 C106.1 C113.1 C142.2 C144.2 C145.2 C148.2 CAMERA.20 CN1.2 CN1.3 COM0.5 COM3.5 CON1.4 CON2.6 CON3.4 CON4.4 CON5.2 CON5.3 CON6.8 CON8.4(GND1) CON8.9(GND2) CON8.15(GND3) CON8.18(GND4) CON8.21(GND5) CON8.26(GND6) CON8.27(GND7) CON8.29(GND8) CON8.34(GND9) CON8.35(GND10) CON8.37(GND11) CON8.40(GND12) CON8.43(GND13) CON8.M1 CON8.M2 CON10.3(GND2) CON10.6(GND1) CON10.12(PAD1) CON10.13(PAD2) H1.1 H2.1 H3.1 H4.1 H5.1 H6.1 H7.1 H8.1 H9.1 H10.1 H11.1 H12.1 H13.1 H14.1 K1.2 K2.2 K3.2 K4.2 K5.2 K6.2 K7.2 K8.2 L9.2 LCD1.11(GND1) LCD1.20(GND2) LCD1.29(GND3) LCD1.37(GND4) LCD1.38(GND5) LCD1.39(GND6) LCD1.40(GND7) LCD1.45(GND8) LCD1.A LCD1.B LCD2.11(GND1) LCD2.20(GND2) LCD2.29(GND3) LCD2.A LCD2.B LCD3.11(GND1) LCD3.20(GND2) LCD3.29(GND3) LCD3.A LCD3.B LCD4.11 LCD4.20 LCD4.29 LCD4.37 LCD4.38 LCD4.39 LCD4.40 LED_3.3.2(CATHODE) MINIUSB1.5(GND) MINIUSB1.6(#6) MINIUSB1.7(#7) MINIUSB1.8(#8) MINIUSB1.9(#9) P1.4(GND) Q2.E(EMITTER) R3.1 R8.2 R16.1 R63.1 R91.2 R93.2 R94.2 R99.2 R109.2 R111.1 R113.2 R115.1 R116.1 R117.1 R121.2 R135.2 R136.2 R139.1 R142.1 RST.2 SDIO.2 SDIO.A SDIO.B TINY210.A2 TINY210.C20 U2.1(GND) U4.5(AGND2) U4.6(AGND3) U4.15(GND) U4.33(GND2) U4.41(TEST) U4.45(GND1) U4.47(AGND1) U4.48(BGGND) U5.1(A0) U5.2(A1) U5.3(A2) U5.4(GND) U5.7(WP) U6.9(DGND) U6.G1(GND_PADDLE) U7.1(RESERVED1) U7.4(AVSS) U7.8(DVSS) U8.15(VSS) U9.19(DGND) U11.11(TEST) U11.37(VSS(FLAG)) USBH1.4(GND1) USBH1.5(GND3) USBH1.6(GND2) USBH2.4(GND1) USBH2.5(GND3) USBH2.6(GND2) USBH3.4(GND1) USBH3.5(GND3) USBH3.6(GND2) W1.1(A)
GND_EARTH: C21.2 LAN1.8(CHS_GND)
VBAT: BAT1.1(+) D1.2(K) R11.1
VDD_3.3V: C10.1 C11.1 C15.1 C16.1 C17.1 C18.1 C27.1 C28.1 C62.2 C67.1 C68.1 C79.1 C142.1 C144.1 C145.1 C148.1 CON6.1 CON8.2(VDD_3V3A) CON8.24(VDD_3V3B) CON8.39(VDD_3V3C) CON8.41(VDD_3V3D) CON8.52(VDD_3V3E) CON10.4(VDD) D1.1(A) D4.1(ANODE) FB1.1 FB2.1 FB5.1 J1.2 R4.1 R5.2 R9.1 R10.1 R12.2 R13.2 R14.2 R18.2 R19.2 R20.1 R21.1 R23.1 R27.1 R28.1 R30.1 R31.2 R32.2 R34.1 R35.2 R37.2 R38.2 R39.2 R40.2 R41.2 R42.2 R43.1 R49.2 R60.1 R64.1 R65.1 R66.1 R71.2 R72.2 R73.2 R74.2 R75.2 R107.2 R108.2 R114.2 R118.2 R119.2 R126.2 R127.2 R128.2 R129.2 R131.2 R132.2 R133.2 R134.2 SDIO.1 U2.2(Vout) U2.4(TAB) U4.23(VDD1) U4.30(VDD2) U4.42(VDD3) U5.8(VDD) U7.3(AVDD) U7.9(DVDD) U8.16(VDD) W1.2(B)
VDD_5V: BUZZER1.1 C8.1 C9.1 C73.1 C96.1 C97.1 CON1.3 CON2.5 CON3.3 CON4.3 CON5.1 FB3.1 LCD1.1(VDD5V) LCD1.2(VDD5V) LCD2.1(VDD5V) LCD2.2(VDD5V) LCD3.1(VDD5V) LCD3.2(VDD5V) LCD4.1 LCD4.2 S1.2 TINY210.A1 U2.3(Vin) USBH1.1(VBUS) USBH2.1(VBUS) USBH3.1(VBUS)
VDD_AUDIO_A3.3V: C31.1 C32.1 FB2.2 U6.32(AVDD)
VDD_AUDIO_D3.3V: C50.1 C54.1 FB5.2 U6.8(DCVDD) U6.10(DBVDD)
VDD_AUDIO_SPK: C29.1 C30.1 FB1.2 FB3.2 U6.21(SPKVDD2) U6.26(SPKVDD1)
VDD_CAM_1.8V: C106.2 CAMERA.19 L8.1 TINY210.C19 U9.20(DVDD)
VDD_CAM_2.5V: CAMERA.18 TINY210.C18
VDD_CCD_3.3V: C105.2 J1.1 R143.1 R144.2 R145.1 R146.1 U9.10(IO_DVDD)
VDD_CMOS_3.3V: CAMERA.17 J1.3
VDD_IN: CN1.1 CON5.4 S1.3
VDD_RTC_AP: R11.2 TINY210.B4
Audio_Xi2sCDCLK0: R133.1 TINY210.B30 U6.11(MCLK)
Audio_Xi2sLRCK0: R131.1 TINY210.B31 U6.13(DACLRC)
Audio_Xi2sSCLK0: R132.1 TINY210.B29 U6.12(BCLK)
Audio_Xi2sSDI0: R128.1 TINY210.B33 U6.16(ADCDAT)
Audio_Xi2sSDO0_0: R129.1 TINY210.B32 U6.14(DATDAT)
CAM_A_RESET: C113.2 CAMERA.4 R146.2 TINY210.C4 U9.8(~{RESETB})
CAM_SCL0: CAMERA.2 R140.1 TINY210.C2
CAM_SDA0: CAMERA.1 R141.1 TINY210.C1
CAMERA_A_GPIO2: CAMERA.3 TINY210.C3
CCD_AGND: AVIN.3(GND) C65.2 C104.2 C107.1 C108.2 C109.2 C111.1 C112.1 L9.1 R51.2 U9.3(PLL_AGND) U9.7(NSUB) U9.31(CH1_AGND)
CCD_SCL: R140.2 R143.2 U9.21(SCL)
CCD_SDA: R141.2 R144.1 U9.22(SDA)
DM2-: R110.1 U11.3(USBDN2_DM)
DM3-: R95.1 U11.6(USBDN3_DM)
DM4-: R89.1 U11.8(USBDN4_DM)
DM9000_RX+: LAN1.3(RX+) R26.1 U4.3(RX+)
DM9000_RX-: LAN1.6(RX-) R29.1 U4.4(RX-)
DM9000_TX+: LAN1.1(TD+) R24.1 U4.7(TX+)
DM9000_TX-: LAN1.2(TD-) R25.1 U4.8(TX-)
DP2+: R112.1 U11.4(USBDN2_DP)
DP3+: R97.1 U11.7(USBDN3_DP)
DP4+: R90.1 U11.9(USBDN4_DP)
Earphone_detect: C35.1 R49.1 R92.1 SPK1.2(B)
HS_IND/CFG_SEL1: R115.2 R134.1 U11.25(HS_IND/CFG_SEL1)
LANLED: LAN1.11(LEDY-) U4.39(LED1)
LINKLED: LAN1.10(LEDG-) U4.38(LED2)
LOCAL_PWR: R111.2 U11.28(SUSP_IND/LOCAL_PWR/NON_REM0)
M_nRESET: RST.1 TINY210.B3
MICBIAS: C59.2 C60.1 R59.2 U6.1(MICBIAS)
NET_AVDD25: C22.1 C23.1 C24.1 LAN1.4(CT2) LAN1.5(CT1) U4.2(AVDD25) U4.9(AVDD25_1)
nRESET: C83.1 R114.1 U11.26(~{RESET})
nWAIT: R5.1 TINY210.B41
OM1: R1.2 TINY210.B1
RBIAS: R121.1 U11.35(RBIAS)
RSRXD0: COM0.2 U8.13(RIN1)
RSRXD3: COM3.2 U8.8(RIN2)
RSTXD0: COM0.3 U8.14(T1OUT)
RSTXD3: COM3.3 U8.7(T2OUT)
SCL/CFG_SEL0: R107.1 R116.2 U11.24(SCL/SMBCLK/CFG_SEL0)
SDA: R108.1 R117.2 U11.22(SDA/SMBDATA/NON_REM1)
SPK_OUT_LN: C38.1 CON12.2 U6.23(SPK_LN)
SPK_OUT_LP: C37.1 CON12.1 U6.25(SPK_LP)
SPK_OUT_RN: C48.1 CON12.3 U6.19(SPK_RN)
SPK_OUT_RP: C47.1 CON12.4 U6.22(SPK_RP)
USB_D+: R80.2 U11.2(USBDN1_DP)
USB_D-: R81.2 U11.1(USBDN1_DM)
USIM_CLK: C76.1 CON8.12(USIM_CLK) P1.3(CLK)
USIM_DATA: C77.1 CON8.10(USIM_DATA) P1.6(DATA)
USIM_RST: C78.1 CON8.14(USIM_RESET) P1.2(RST)
USIM_VCC: C75.1 CON8.8(USIM_POWER) P1.1(VCC)
W_DISABLE_N: CON8.20(W_DISABLE_N) R75.1
WiFi0_PD_GPIO: R12.1 SDIO.11 TINY210.A41
WiFi0_RESET_GPIO: R27.2 SDIO.12 TINY210.A42
XadcAIN0: C64.1 CON6.2 TINY210.A39 W1.3(WIPER)
XadcAIN1: CON6.3 TINY210.A40
XadcAIN6_YM: CON6.4 TINY210.A38
XadcAIN7_YP: CON6.5 TINY210.A37
XadcAIN8_XM: CON6.6 TINY210.A36
XadcAIN9_XP: CON6.7 TINY210.A35
XciCLKenb: CAMERA.5 TINY210.C5
XciHREF: CAMERA.6 R137.2 R138.2 TINY210.C6
XciPCLK: CAMERA.8 TINY210.C8 U9.9(SCLK)
XciVSYNC: CAMERA.7 TINY210.C7 U9.24(VSYNC/PALI)
XciYDATA0: CAMERA.16 TINY210.C16 U9.18(YOUT0)
XciYDATA1: CAMERA.15 TINY210.C15 U9.17(YOUT1)
XciYDATA2: CAMERA.14 TINY210.C14 U9.16(YOUT2)
XciYDATA3: CAMERA.13 TINY210.C13 U9.15(YOUT3)
XciYDATA4: CAMERA.12 TINY210.C12 U9.14(YOUT4)
XciYDATA5: CAMERA.11 TINY210.C11 U9.13(YOUT5)
XciYDATA6: CAMERA.10 TINY210.C10 U9.12(YOUT6)
XciYDATA7: CAMERA.9 R139.2 TINY210.C9 U9.11(YOUT7/I2CSEL)
XdacOUT: TINY210.A51
XEINT6_SD0_nWP: CON10.10(WP) TINY210.B24
XEINT7: TINY210.B40 U4.34(INT)
XEINT8: TINY210.A30
XEINT9: R28.2 SDIO.16 TINY210.B34
XEINT10: LCD1.31(EINT10) LCD2.31(EINT10) LCD3.31(EINT10) LCD4.31 TINY210.A22
XEINT11: R30.2 TINY210.A46 U7.5(~{INT})
XEINT14: LCD1.43(EINT14) LCD4.43 TINY210.C24
XEINT15: LCD1.44(EINT15) LCD4.44 TINY210.C22
XEINT16/KP_COL0: CON7.1 K1.1 R35.1 TINY210.A53
XEINT17/KP_COL1: CON7.2 K2.1 R37.1 TINY210.A54
XEINT18/KP_COL2: CON7.3 K3.1 R39.1 TINY210.A55
XEINT19/KP_COL3: CON7.4 K4.1 R40.1 TINY210.A56
XEINT24/KP_ROW0: CON7.5 K5.1 R43.2 TINY210.A57
XEINT25/KP_ROW1: CON7.6 K6.1 R64.2 TINY210.A58
XEINT26/KP_ROW2: CON7.7 K7.1 R65.2 TINY210.A59
XEINT27/KP_ROW3: CON7.8 K8.1 R66.2 TINY210.A60
Xi2cSCL0: R9.2 R31.1 R57.1 R127.1 SDIO.5 TINY210.B19 U5.6(SCL) U7.6(SCL)
Xi2cSCL2/IEM_SPWI: LCD1.41(SCL2) LCD4.41 TINY210.C23
Xi2cSDA0: R10.2 R32.1 R58.1 R126.1 SDIO.6 TINY210.B20 U5.5(SDA) U7.7(SDA)
Xi2cSDA2/IEM_SCLK: LCD1.42(SDA2) LCD4.42 TINY210.C21
Xm0ADDR0: TINY210.B35
Xm0ADDR1: TINY210.B36
Xm0ADDR2: R7.2 TINY210.B37
Xm0ADDR3: TINY210.B38
Xm0CSn1: TINY210.B39 U4.37(CS#)
Xm0DATA0: TINY210.B45 U4.18(SD0)
Xm0DATA1: TINY210.B46 U4.17(SD1)
Xm0DATA2: TINY210.B47 U4.16(SD2)
Xm0DATA3: TINY210.B48 U4.14(SD3)
Xm0DATA4: TINY210.B49 U4.13(SD4)
Xm0DATA5: TINY210.B50 U4.12(SD5)
Xm0DATA6: TINY210.B51 U4.11(SD6)
Xm0DATA7: TINY210.B52 U4.10(SD7)
Xm0DATA8: TINY210.B53 U4.31(SD8)
Xm0DATA9: TINY210.B54 U4.29(SD9)
Xm0DATA10: TINY210.B55 U4.28(SD10)
Xm0DATA11: TINY210.B56 U4.27(SD11)
Xm0DATA12: TINY210.B57 U4.26(SD12)
Xm0DATA13: TINY210.B58 U4.25(SD13)
Xm0DATA14: TINY210.B59 U4.24(SD14)
Xm0DATA15: TINY210.B60 U4.22(SD15)
Xm0OEn: TINY210.B44 U4.35(IOR#)
Xm0WEn: TINY210.B43 U4.36(IOW#)
Xmmc0CDn: CON10.11(nCD) R71.1 TINY210.B23
Xmmc0DATA0: CON10.7(DAT0) R73.1 TINY210.B25
Xmmc0DATA1: CON10.8(DAT1) R72.1 TINY210.B26
Xmmc0DATA2: CON10.9(DAT2) R74.1 TINY210.B27
Xmmc0DATA3: CON10.1(CD/DAT3) R38.1 TINY210.B28
Xmmc2CDn/SPI_MISO2: R14.1 SDIO.15 TINY210.A45
Xmmc2CLK/SPI_CLK2: R13.1 SDIO.13 TINY210.A43
Xmmc2CMD/SPI_CSn2: R23.2 SDIO.14 TINY210.A44
Xmmc2DATA0/SPI_MOSI2: R18.1 SDIO.17 TINY210.A47
Xmmc2DATA1: R34.2 SDIO.18 TINY210.A48
Xmmc2DATA2: R19.1 SDIO.19 TINY210.A49
Xmmc2DATA3: R60.2 SDIO.20 TINY210.A50
XmmcCLK0: CON10.5(CLK) R41.1 TINY210.B21
XmmcCMD0: CON10.2(CMD) R42.1 TINY210.B22
XnRSTOUT: LCD1.32(nRESET) LCD2.32(nRESET) LCD3.32(nRESET) LCD4.32 TINY210.B42 U4.40(PWRST#)
XpwmTOUT0: R6.2 TINY210.A52
XpwmTOUT1: LCD1.30(TOUT1) LCD2.30(TOUT1) LCD3.30(TOUT1) LCD4.30 TINY210.A26
XspiCKL1: SDIO.9 TINY210.B17
XspiCS1: SDIO.10 TINY210.B18
XspiMISO1: SDIO.8 TINY210.B16
XspiMOSI1: SDIO.7 TINY210.B15
XuCTSn1: CON2.2 TINY210.B6
XuhDM: R96.2 TINY210.A32
XuhDP: R82.2 TINY210.A34
XuoDM: MINIUSB1.2(D-) TINY210.A31
XuoDP: MINIUSB1.3(D+) TINY210.A33
XuoDRVVBUS: TINY210.A28
XuoID: MINIUSB1.4(ID) TINY210.A29
XuoVBUS: C51.1 C52.1 MINIUSB1.1(VBUS) TINY210.A27
XuRTSn1: CON2.1 TINY210.B5
XuRXD0: CON1.2 TINY210.B8 U8.12(ROUT1)
XuRXD1: CON2.4 TINY210.B10
XuRXD2: CON3.2 SDIO.4 TINY210.B12
XuRXD3: CON4.2 TINY210.B14 U8.9(ROUT2)
XuTXD0: CON1.1 TINY210.B7 U8.11(T1IN)
XuTXD1: CON2.3 TINY210.B9
XuTXD2: CON3.1 SDIO.3 TINY210.B11
XuTXD3: CON4.1 TINY210.B13 U8.10(T2IN)
XvHSYNC: LCD1.35(HSYNC) LCD2.35(HSYNC) LCD3.35(HSYNC) LCD4.35 TINY210.A24
XvVCLK: LCD1.36(VCLK) LCD2.36(VCLK) LCD3.36(VCLK) LCD4.36 TINY210.A25
XvVD0: LCD1.3(VD0) LCD2.3(VD0) LCD3.3(VD0) LCD4.3 TINY210.C25
XvVD1: LCD1.4(VD1) LCD2.4(VD1) LCD3.4(VD1) LCD4.4 TINY210.C26
XvVD2: LCD1.5(VD2) LCD2.5(VD2) LCD3.5(VD2) LCD4.5 TINY210.A20
XvVD3: LCD1.6(VD3) LCD2.6(VD3) LCD3.6(VD3) LCD4.6 TINY210.A19
XvVD4: LCD1.7(VD4) LCD2.7(VD4) LCD3.7(VD4) LCD4.7 TINY210.A18
XvVD5: LCD1.8(VD5) LCD2.8(VD5) LCD3.8(VD5) LCD4.8 TINY210.A17
XvVD6: LCD1.9(VD6) LCD2.9(VD6) LCD3.9(VD6) LCD4.9 TINY210.A16
XvVD7: LCD1.10(VD7) LCD2.10(VD7) LCD3.10(VD7) LCD4.10 TINY210.A15
XvVD8: LCD1.12(VD8) LCD2.12(VD8) LCD3.12(VD8) LCD4.12 TINY210.C27
XvVD9: LCD1.13(VD9) LCD2.13(VD9) LCD3.13(VD9) LCD4.13 TINY210.C28
XvVD10: LCD1.14(VD10) LCD2.14(VD10) LCD3.14(VD10) LCD4.14 TINY210.A14
XvVD11: LCD1.15(VD11) LCD2.15(VD11) LCD3.15(VD11) LCD4.15 TINY210.A13
XvVD12: LCD1.16(VD12) LCD2.16(VD12) LCD3.16(VD12) LCD4.16 TINY210.A12
XvVD13: LCD1.17(VD13) LCD2.17(VD13) LCD3.17(VD13) LCD4.17 TINY210.A11
XvVD14: LCD1.18(VD14) LCD2.18(VD14) LCD3.18(VD14) LCD4.18 TINY210.A10
XvVD15: LCD1.19(VD15) LCD2.19(VD15) LCD3.19(VD15) LCD4.19 TINY210.A9
XvVD16: LCD1.21(VD16) LCD2.21(VD16) LCD3.21(VD16) LCD4.21 TINY210.C29
XvVD17: LCD1.22(VD17) LCD2.22(VD17) LCD3.22(VD17) LCD4.22 TINY210.C30
XvVD18: LCD1.23(VD18) LCD2.23(VD18) LCD3.23(VD18) LCD4.23 TINY210.A8
XvVD19: LCD1.24(VD19) LCD2.24(VD19) LCD3.24(VD19) LCD4.24 TINY210.A7
XvVD20: LCD1.25(VD20) LCD2.25(VD20) LCD3.25(VD20) LCD4.25 TINY210.A6
XvVD21: LCD1.26(VD21) LCD2.26(VD21) LCD3.26(VD21) LCD4.26 TINY210.A5
XvVD22: LCD1.27(VD22) LCD2.27(VD22) LCD3.27(VD22) LCD4.27 TINY210.A4
XvVD23: LCD1.28(VD23) LCD2.28(VD23) LCD3.28(VD23) LCD4.28 TINY210.A3
XvVDEN: LCD1.33(VDEN) LCD2.33(VDEN) LCD3.33(VDEN) LCD4.33 TINY210.A21
XvVSYNC: LCD1.34(VSYNC) LCD2.34(VSYNC) LCD3.34(VSYNC) LCD4.34 TINY210.A23
N490506: R57.2 U6.17(SCLK)
N490846: R58.2 U6.18(SDIN)
N563338: C46.1 U6.6(RINPUT2)
N563659: C45.1 U6.7(RINPUT3/JD3)
N565258: C44.1 U6.2(LINPUT3/JD2)
N570115: C43.1 U6.5(RINPUT1)
N579751: C36.2 U6.4(LINPUT1)
N580413: C36.1 C41.1 R59.1 R62.2 R67.2
N605417: C34.1 C55.2 R46.2 SPK1.3(C) SPK1.4(D)
N617320: C33.1 C56.2 R47.2 SPK1.1(A)
N3676300: R1.1 R2.2 S2.3
N3676952: R2.1 TINY210.B2
N3684154: R3.2 S2.4
N3805887: LED_3.3.1(ANODE) R4.2
N3869369: R7.1 U4.32(CMD)
N3921053: C19.1 U4.43(X2) Y1.1
N3921204: C20.1 U4.44(X1) Y1.2
N3925254: R8.1 U4.1(BGRES)
N3968686: C25.1 R24.2 R25.2
N3970814: C26.1 R26.2 R29.2
N3982722: LAN1.9(LEDG+) R20.2
N3983324: LAN1.12(LEDY+) R21.2
N4027687: Q2.B(BASE) R6.1 R16.2
N4771984: C42.2 U6.3(LINPUT2)
N5234173: R92.2 U6.15(ADCLRC/GPIO1)
N5390728: C55.1 U6.31(HP_L)
N5390947: C56.1 U6.29(HP_R)
N5424123: C57.2 C58.1 U6.27(VMID)
N6095373: C39.2 U8.1(C1+)
N6095738: C39.1 U8.3(C1-)
N6103030: C40.2 U8.2(V+)
N6103395: C49.2 U8.6(V-)
N6105619: C61.1 U8.4(C2+)
N6105986: C61.2 U8.5(C2-)
N6195963: BUZZER1.2 Q2.C(COLLECTOR)
N9607388: R96.1 R136.1 U11.30(USBUP_DM)
N9607392: R82.1 R135.1 U11.31(USBUP_DP)
N9607432: C95.1 R130.2 U11.33(XTAL1/CLKIN) Y3.2
N9607572: C80.1 C82.1 C86.1 C87.1 C88.1 C89.1 C93.1 C94.1 R118.1 U11.5(VDDA33) U11.10(VDDA33) U11.15(VDD33(REG)) U11.23(VDD33(IO)) U11.29(VDDA33) U11.36(VDDPLLREF/VDDA33)
N9607910: C81.1 R130.1 U11.32(XTAL2/CLKIN_EN) Y3.1
N9607998: C85.1 R119.1 U11.27(VBUS_DET)
N9608162: C84.1 C90.1 U11.34(PLLFILT)
N9608206: C91.1 C92.1 U11.14(CRFILT)
N9608680: R89.2 R91.1 USBH1.2(D-)
N9608700: R90.2 R93.1 USBH1.3(D+)
N9608868: R94.1 R95.2 USBH2.2(D-)
N9608880: R97.2 R99.1 USBH2.3(D+)
N9609084: R109.1 R110.2 USBH3.2(D-)
N9609088: R112.2 R113.1 USBH3.3(D+)
N9616349: CON8.36(USB_DM) R81.1
N9616353: CON8.38(USB_DP) R80.1
N9617073: CON8.22(PERST_N) PERST_N.1
N9617077: CON8.42(LED_WWAN_N) R76.1
N9617165: D4.2(CATHODE) R76.2
N9621622: AVIN.1(OUT) AVIN.2 C104.1 L6.1
N9621696: R142.2 R145.2 U9.28(PDN)
N9622060: C53.2 U9.1(AIP1A)
N9622080: C63.2 U9.2(AIP1B)
N9622122: C53.1 C63.1 C65.1 L6.2 R51.1
N9622404: C109.1 U9.5(XTAL/OSC) Y2.1
N9622412: C108.1 U9.6(XTAL2) Y2.2
N9622484: C110.2 C112.2 U9.30(REFM)
N9622488: C110.1 C111.2 U9.29(REFP)
N9622590: R137.1 U9.26(AVID)
N9622630: R138.1 U9.25(HSYNC)
N9633247: MIC2.1(A) MIC2.4(D) R67.1
N9633353: MIC1.1 MIC2.2(B) MIC2.3(C)

Not connected (* = marked no-connect by the designer): BAT1 3* 4*; CN1 M1* M2*; COM0 1* 4* 6* 7* 8* 9* 10* 11*; COM3 1* 4* 6* 7* 8* 9* 10* 11*; CON8 1(N/C1) 3(N/C2) 5(N/C3) 6(N/C4) 7(N/C5) 11(N/C6) 13(N/C7) 16(USIM_VPP) 17(N/C8) 19(N/C9) 23(N/C10) 25(N/C11) 28(N/C12) 30(N/C13) 31(N/C14) 32(N/C15) 33(N/C16) 44(N/C17) 45(Reserved1) 46(N/C18) 47(Reserved2) 48(N/C19) 49(Reserved3) 50(N/C20) 51(Reserved4) G1 G2; CON10 14(PAD3)* 15(PAD4)*; K1 3*; K2 3*; K3 3*; K4 3*; K5 3*; K6 3*; K7 3*; K8 3*; LAN1 7(N.C)* M1* M2* M3* M4*; LCD2 37(SCL2) 38(EINT14) 39(SDA2) 40(EINT15); LCD3 37(SCL2) 38(EINT14) 39(SDA2) 40(EINT15); MINIUSB1 10(NC1)* 11(NC2)* M1* M2*; P1 5(VPP)*; RST 3*; S1 1* 4* 5*; S2 1* 2* 5*; TINY210 C17*; U4 19(EEDIO)* 20(EECK)* 21(EECS)* 46(SD)*; U6 30(OUT3)*; U7 2(N/C) 10(RESERVED2) M1 M2; U9 23(FID/GLCO)* 27(INTERQ/GPCL/VBLK)*; U11 12(PRTPWR1)* 13(~{OCS1})* 16(PRTPWR2)* 17(~{OCS2})* 18(PRTPWR3)* 19(~{OCS3})* 20(PRTPWR4)* 21(~{OCS4})*

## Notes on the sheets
sheet 1
- CoreBoard
- 5V Power In
- 3.3V Power Supply
- （红色）
sheet 2
- Ethernet:DM9000AEP
- LQFP48
sheet 3
- Audio Codec
- 绿色
- R201=680 Ohm to 2.2kOhm
  check microphone's specification
- 蓝色
sheet 4
- AD-Convert
- PWM Buzzer
- RTC
- I2C-Eeprom
- SDIO
- BACK
- HOME
- Buttons
- MENU
- USB Slave
- 针座
sheet 5
- LCD
- SDCARD
- UART
- 公座
- G-Sensor
- 公座
- 不焊
sheet 6
- Camera
- 针座
sheet 7
- USB HUB
- VDDA33
sheet 9
- HOLES
